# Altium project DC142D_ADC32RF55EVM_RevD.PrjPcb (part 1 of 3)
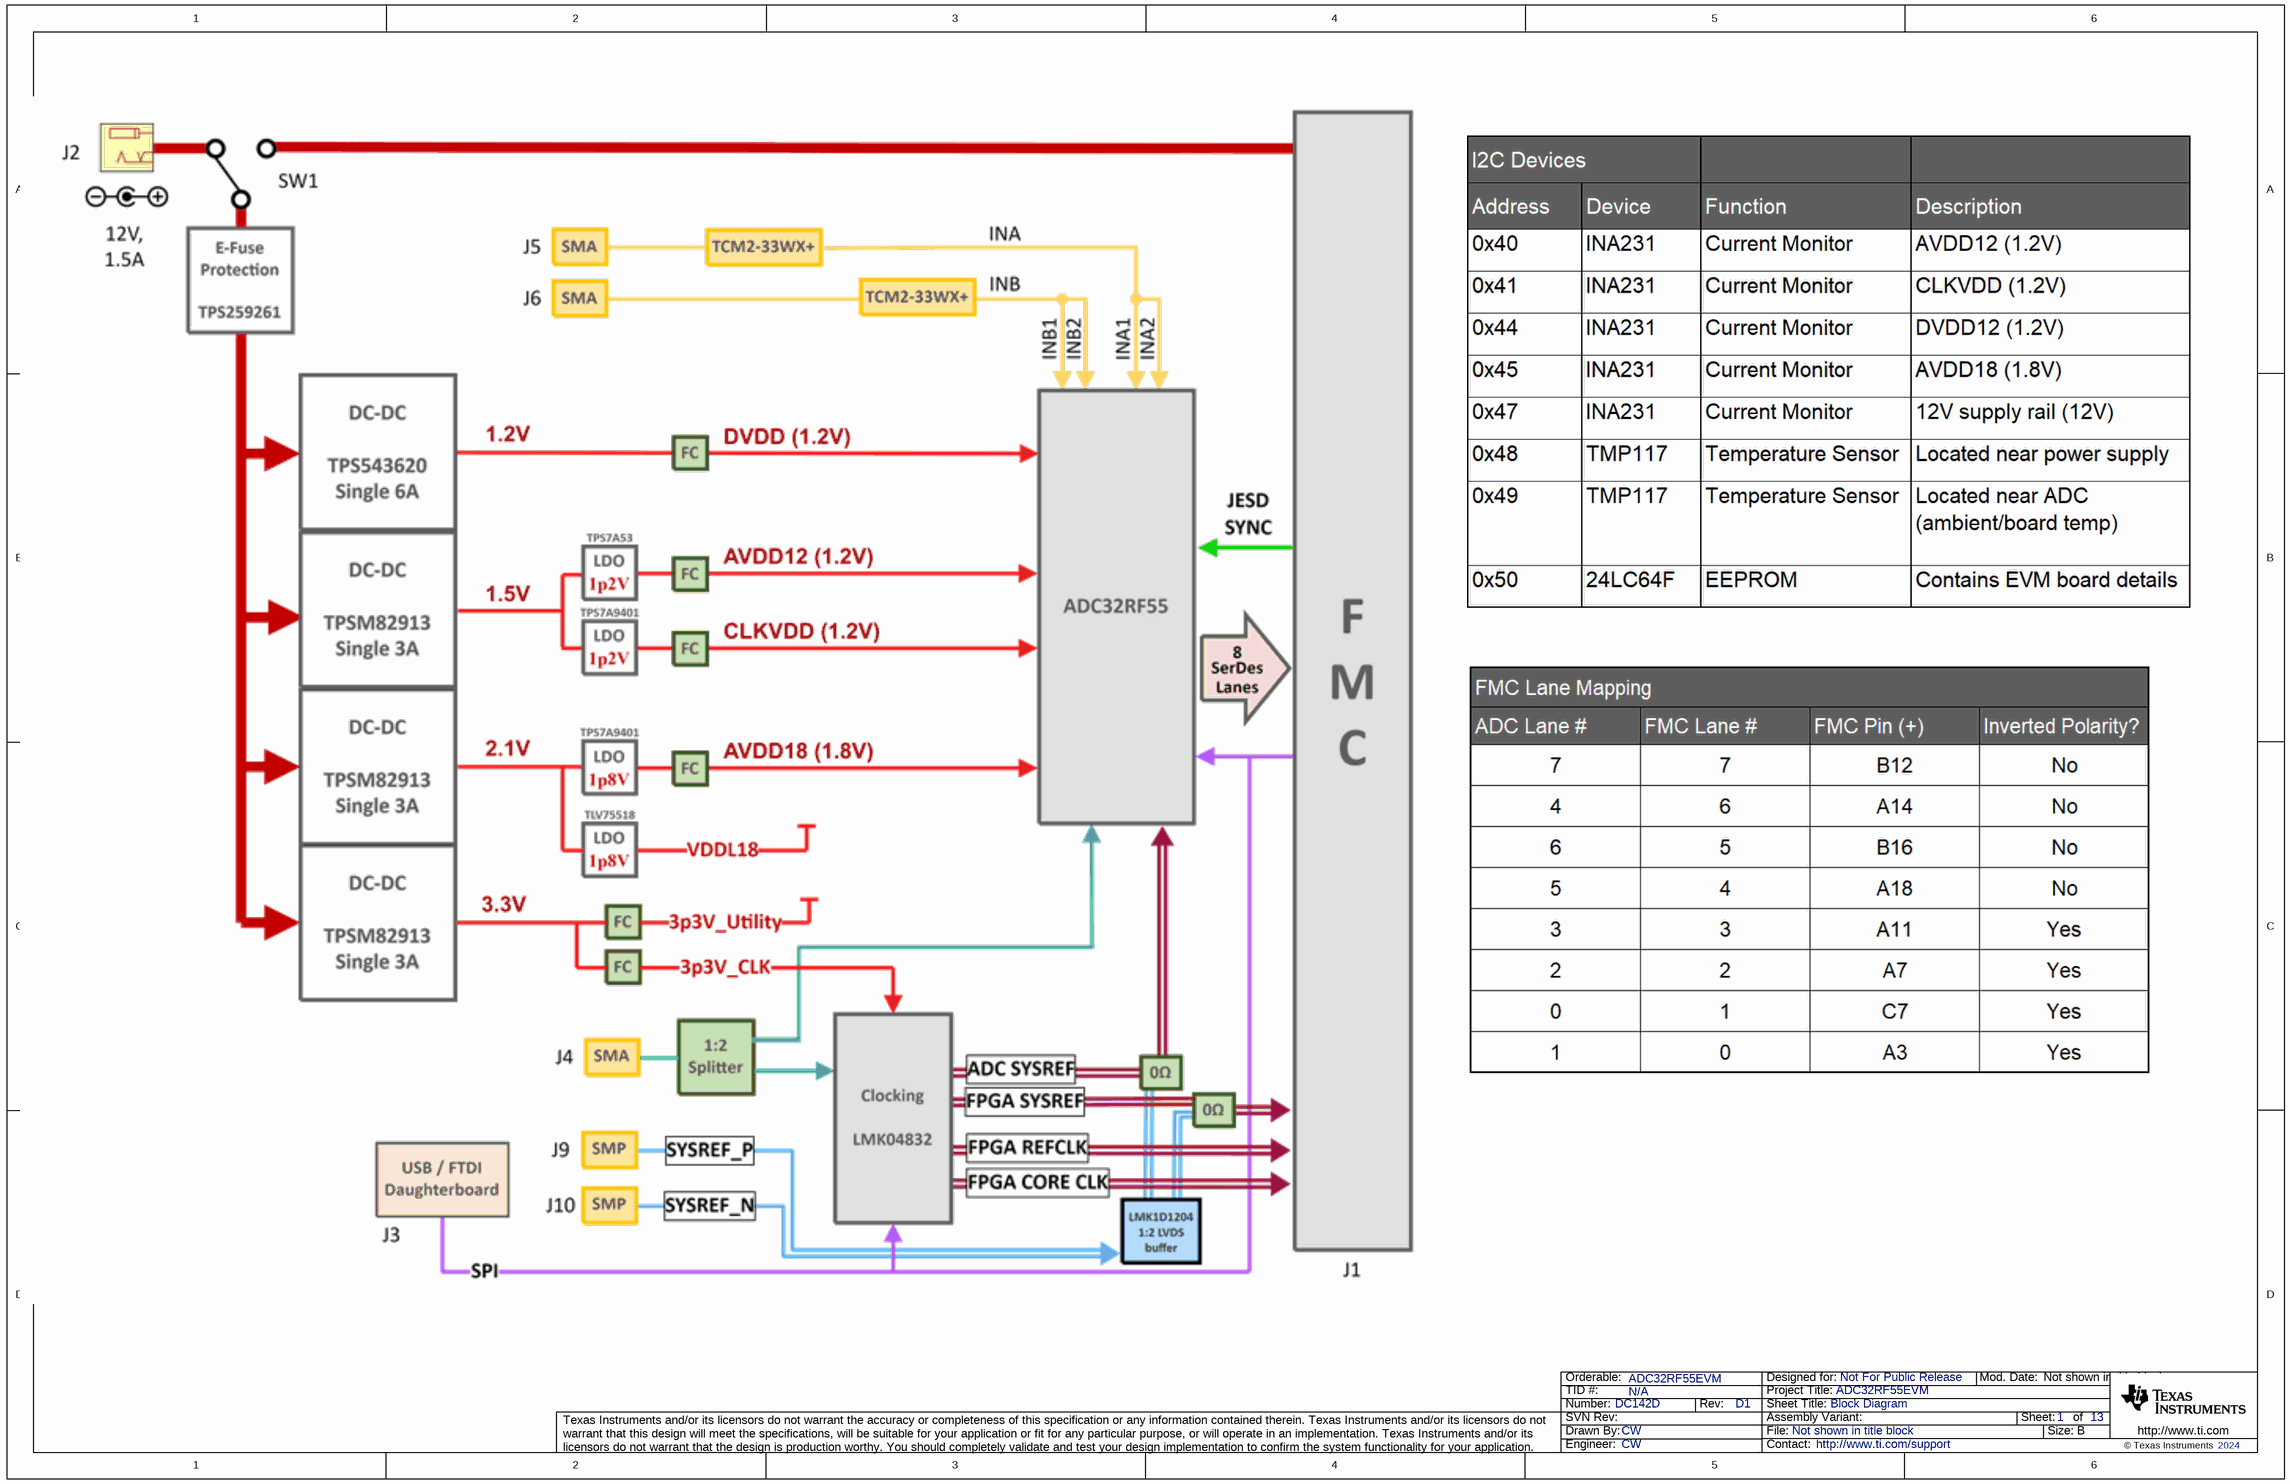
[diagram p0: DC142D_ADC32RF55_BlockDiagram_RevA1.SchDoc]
BrdNum: DC142; CopyrightYear: 2024; EVM_Orderable: ADC32RF55EVM; PCB_Layout: CW; PCB_Rev: D1; PRJ_Customer: Not For Public Release; PRJ_Engineer: CW; PRJ_Number: DC142D; PRJ_Title: ADC32RF55EVM; SCH_Rev: D1; TechSupport: http://www.ti.com/support; TID: N/A
13 sheets, 433 parts. Net scope: flat (ports and power ports of the same name join across sheets).
Board file: ADC32RF55EVM_RevD.PcbDoc
Sheets:
  DC142D_ADC32RF55_BlockDiagram_RevA1.SchDoc
  DC142D_ADC32RF55_Power1_RevA1.SchDoc
  DC142D_ADC32RF55_Power2_RevA1.SchDoc
  DC142D_ADC32RF55_Power3_RevA1.SchDoc
  DC142D_ADC32RF55_USB_RevA1.SchDoc
  DC142D_ADC32RF55_MUX_RevA1.SchDoc
  DC142D_ADC32RF55_ADC_Input_RevA1.SchDoc
  DC142D_ADC32RF55_ADC_Dig_RevA1.SchDoc
  DC142D_ADC32RF55_ADC_Power_RevA1.SchDoc
  DC142D_ADC32RF55_LMK_RevA1.SchDoc
  DC142D_ADC32RF55_FMC_RevA1.SchDoc
  DC142D_ADC32RF55_Misc_RevA1.SchDoc
  DC142D_ADC32RF55_Revision History.SchDoc

## Sheet DC142D_ADC32RF55_BlockDiagram_RevA1.SchDoc: Block Diagram
size 431 x 279 mm; Date: Not shown in title block; ApprovedBy: Not shown in title block; CheckedBy: Not shown in title block; Author: Not shown in title block; CompanyName: Not shown in title block; DrawnBy: CW; Engineer: Not shown in title block; Organization: Not shown in title block; Address1: Not shown in title block; Address2: Not shown in title block; Address3: Not shown in title block; Address4: Not shown in title block; DocumentNumber: 1; Revision: Use project parameter SCH_Rev; SheetNumber: 1; SheetTotal: 13; PageSetup: Record=PageOptions¦CenterHorizontal=True¦CenterVertical=True¦PrintScale=1.00¦XCorrection=1.00¦YCorrection=1.00¦PrintKind=0¦BorderSize=5000000¦LeftOffset=0¦BottomOffset=0¦Orientation=2¦PaperLength=1000¦PaperWidth=1000¦Scale=100¦PaperSource=15¦PrintQuality=600¦MediaType=1¦DitherType=10¦PaperKind=Letter¦PrintScaleMode=1

## Sheet DC142D_ADC32RF55_Power1_RevA1.SchDoc: EVM Power 1
size 431 x 279 mm; Date: Not shown in title block; ApprovedBy: Not shown in title block; CheckedBy: Not shown in title block; Author: Not shown in title block; CompanyName: Not shown in title block; DrawnBy: CW; Engineer: Not shown in title block; Organization: Not shown in title block; Address1: Not shown in title block; Address2: Not shown in title block; Address3: Not shown in title block; Address4: Not shown in title block; DocumentNumber: 6; Revision: Use project parameter SCH_Rev; SheetNumber: 2; SheetTotal: 13; PageSetup: Record=PageOptions¦CenterHorizontal=True¦CenterVertical=True¦PrintScale=1.00¦XCorrection=1.00¦YCorrection=1.00¦PrintKind=0¦BorderSize=5000000¦LeftOffset=0¦BottomOffset=0¦Orientation=2¦PaperLength=1000¦PaperWidth=1000¦Scale=100¦PaperSource=15¦PrintQuality=600¦MediaType=1¦DitherType=10¦PaperKind=Letter¦PrintScaleMode=1
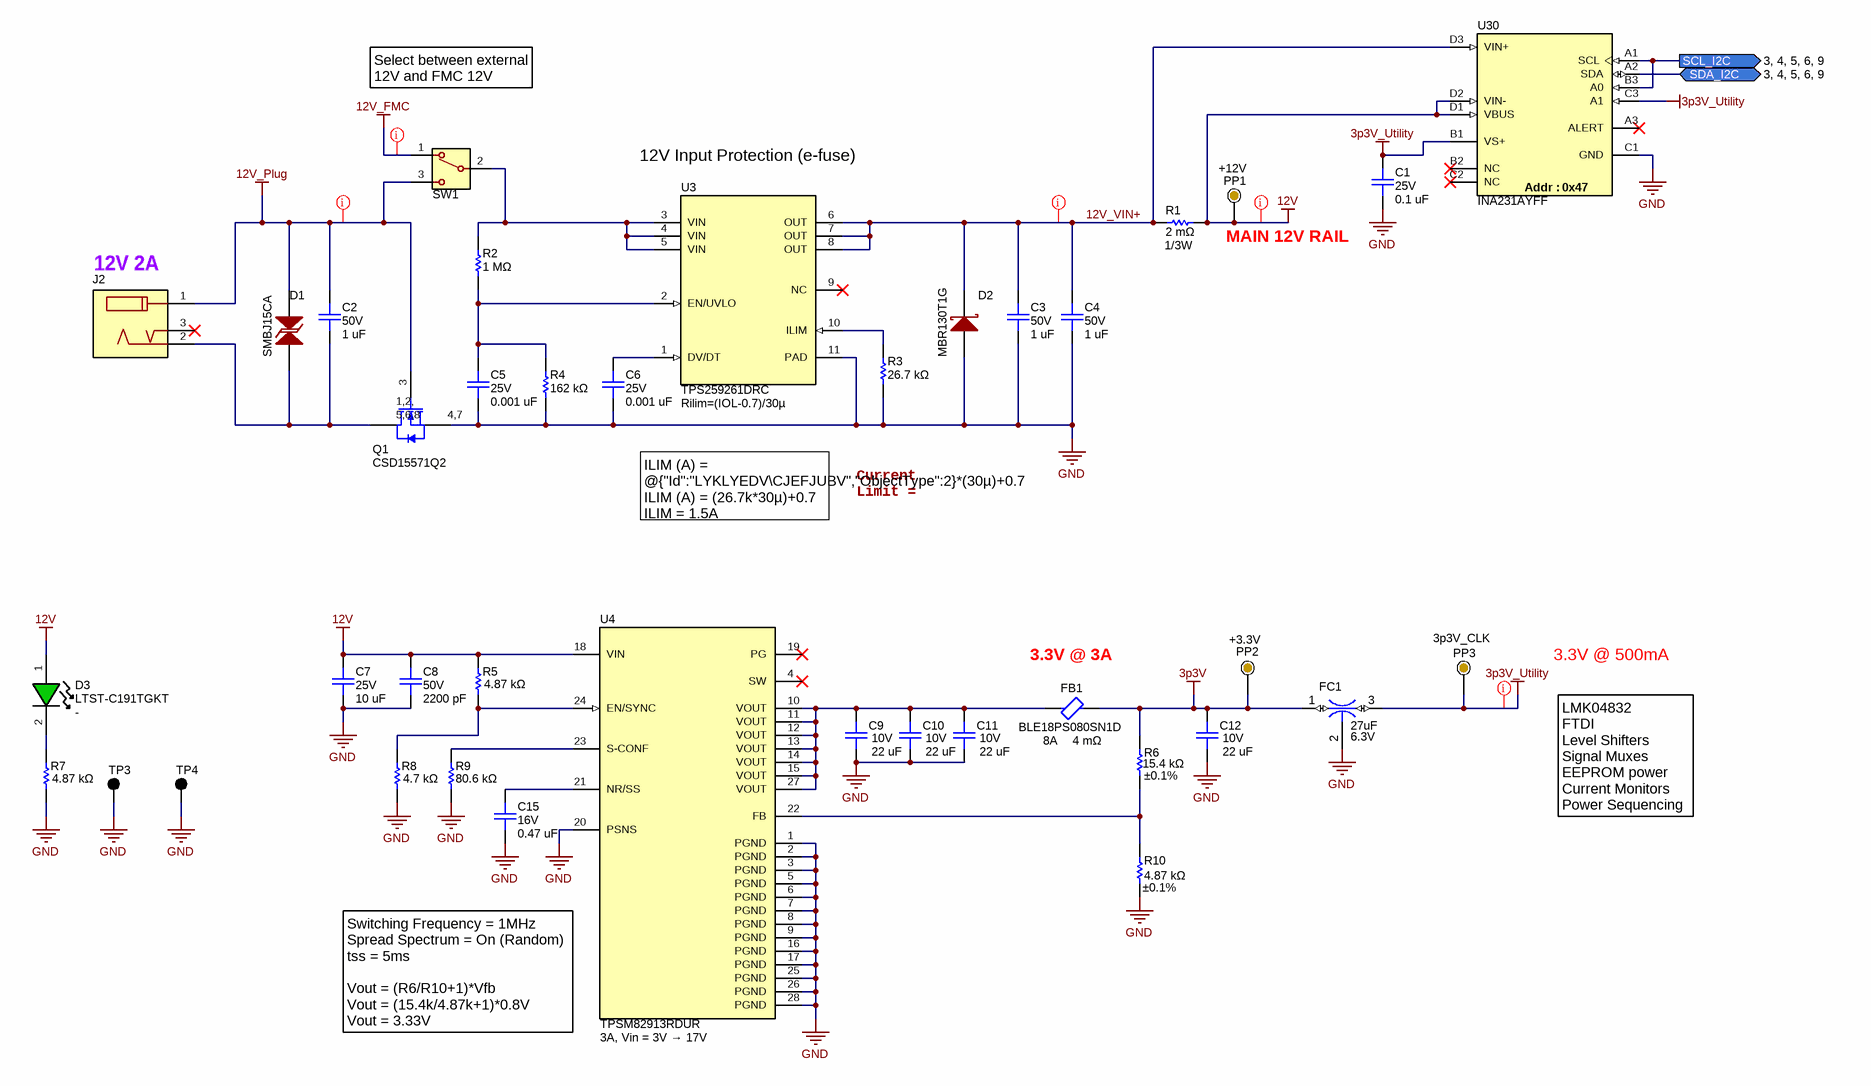
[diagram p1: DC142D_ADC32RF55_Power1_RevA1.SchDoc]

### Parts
C1  value 0.1 uF  Voltage - Rated: 25V  [0402L_cap]  (hidden comment: 04023C104JAT2A)
C2  value 1 uF  Voltage - Rated: 50V  [0805L_cap]  (hidden comment: C2012X7R1H105K125AB)
C3  value 1 uF  Voltage - Rated: 50V  [0805L_cap]  (hidden comment: C2012X7R1H105K125AB)
C4  value 1 uF  Voltage - Rated: 50V  [0805L_cap]  (hidden comment: C2012X7R1H105K125AB)
C5  value 0.001 uF  Voltage - Rated: 25V  [0201_cap]  (hidden comment: 02013C102KAT2A)
C6  value 0.001 uF  Voltage - Rated: 25V  [0201_cap]  (hidden comment: 02013C102KAT2A)
C7  value 10 uF  Voltage - Rated: 25V  [0805L_cap]  (hidden comment: C2012X7S1E106K125AC)
C8  value 2200 pF  Voltage - Rated: 50V  [0402L_cap]  (hidden comment: 04025C222JAT2A)
C9  value 22 uF  Voltage - Rated: 10V  [0805L_cap]  (hidden comment: C2012X7S1A226M125AC)
C10  value 22 uF  Voltage - Rated: 10V  [0805L_cap]  (hidden comment: C2012X7S1A226M125AC)
C11  value 22 uF  Voltage - Rated: 10V  [0805L_cap]  (hidden comment: C2012X7S1A226M125AC)
C12  value 22 uF  Voltage - Rated: 10V  [0805L_cap]  (hidden comment: C2012X7S1A226M125AC)
C15  value 0.47 uF  Voltage - Rated: 16V  [0402L_cap]  (hidden comment: CGA2B1X7S1C474K050BC)
D1  SMBJ15CA  [SMBJ15CA]
D2  MBR130T1G  [SOD-123]
D3  LTST-C191TGKT  [LED_LTST-C190-Green]
FB1  BLE18PS080SN1D  Current: 8A  DCR: 4 mΩ  [0603L]
FC1  value 27uF  Voltage - Rated: 6.3V  [NFM31PC]  (hidden comment: dcp00001)
J2  RAPC722X  [RAPC722X]  (value not drawn)
PP1  Text1: +12V  [ProbePoint_TH_40mil]  (hidden comment: Probe Point)  (no BOM)
PP2  Text1: +3.3V  [ProbePoint_TH_40mil]  (hidden comment: Probe Point)  (no BOM)
PP3  Text1: 3p3V_CLK  [ProbePoint_TH_40mil]  (hidden comment: Probe Point)  (no BOM)
Q1  CSD15571Q2  [DQK0006C]
R1  value 2 mΩ  Power (Watts): 1/3W  [CCS0603FLxLxx]  (hidden comment: CSS0603FT2L00)
R2  value 1 MΩ  [0201]  (hidden comment: ERJ-1GNF1004C)
R3  value 26.7 kΩ  [0201]  (hidden comment: ERJ-1GNF2672C)
R4  value 162 kΩ  [0402L]  (hidden comment: ERJ-2RKF1623X)
R5  value 4.87 kΩ  [0402L]  (hidden comment: ERJ-2RKF4871X)
R6  value 15.4 kΩ  Tolerance: ±0.1%  [0402L]  (hidden comment: ERA-2APB1542X)
R7  value 4.87 kΩ  [0402L]  (hidden comment: ERJ-2RKF4871X)
R8  value 4.7 kΩ  [0402L]  (hidden comment: ERJ-PA2F4701X)
R9  value 80.6 kΩ  [0402L]  (hidden comment: ERJ-2RKF8062X)
R10  value 4.87 kΩ  Tolerance: ±0.1%  [0402L]  (hidden comment: ERA-2APB4871X)
SW1  1101M2S3CGE2  [FP-1101M2S3CGE2_SIP3-MFG]  (value not drawn)
TP3  5011  [Keystone5011]  (value not drawn)
TP4  5011  [Keystone5011]  (value not drawn)
U3  TPS259261DRC  Text1: Rilim=(IOL-0.7)/30µ  [DRC0010J]
U4  TPSM82913RDUR  Text1: 3A, Vin = 3V → 17V  [RDU0028A]
U30  INA231AYFF  Address: 0x47  [YFF0012AKAD]

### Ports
SCL_I2C (out, see 3, 4, 5, 6, 9), SDA_I2C (bidir, see 3, 4, 5, 6, 9)

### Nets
3p3V: C12.2 FB1.2 FC1.1 PP2.1 R6.2
3p3V_Utility: C1.2 FC1.3 PP3.1 U30.B1(VS+) U30.C3(A1)
12V: C7.2 C8.2 D3.1(A) PP1.1 R1.2 R5.1 U4.18(VIN) U30.D1(VBUS) U30.D2(VIN-)
12V_FMC: SW1.1
12V_Plug: C2.1 D1.2 J2.1 Q1.3(G) SW1.3
GND: C1.1 C3.2 C4.2 C5.1 C6.1 C7.1 C8.1 C9.1 C10.1 C11.1 C12.1 C15.1 D2.2(A) FC1.2 Q1.4,7(S) R3.1 R4.2 R7.2 R8.2 R9.1 R10.1 TP3.1 TP4.1 U3.11(PAD) U4.1(PGND) U4.2(PGND) U4.3(PGND) U4.5(PGND) U4.6(PGND) U4.7(PGND) U4.8(PGND) U4.9(PGND) U4.16(PGND) U4.17(PGND) U4.20(PSNS) U4.25(PGND) U4.26(PGND) U4.28(PGND) U30.C1(GND)
12V_VIN+: C3.1 C4.1 D2.1(K) R1.1 U3.6(OUT) U3.7(OUT) U3.8(OUT) U30.D3(VIN+)
SCL_I2C: U30.A1(SCL) U30.B3(A0) ; port SCL_I2C
SDA_I2C: U30.A2(SDA) ; port SDA_I2C
NetC2_2: C2.2 D1.1 J2.2 Q1.1,2,5,6,8(D)
NetC5_2: C5.2 R2.1 R4.1 U3.2(EN/UVLO)
NetC6_2: C6.2 U3.1(DV/DT)
NetC9_2: C9.2 C10.2 C11.2 FB1.1 U4.10(VOUT) U4.11(VOUT) U4.12(VOUT) U4.13(VOUT) U4.14(VOUT) U4.15(VOUT) U4.27(VOUT)
NetC15_2: C15.2 U4.21(NR/SS)
NetD3_2: D3.2(K) R7.1
NetR2_2: R2.2 SW1.2(COMM) U3.3(VIN) U3.4(VIN) U3.5(VIN)
NetR3_2: R3.2 U3.10(ILIM)
NetR5_2: R5.2 R8.1 U4.24(EN/SYNC)
NetR6_1: R6.1 R10.2 U4.22(FB)
NetR9_2: R9.2 U4.23(S-CONF)

Not connected (* = marked no-connect by the designer): J2 3*; U3 9(NC)*; U4 4(SW)* 19(PG)*; U30 A3(ALERT)* B2(NC)* C2(NC)*

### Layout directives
net class Power: 3p3V_Utility, 12V, 12V_FMC, 12V_Plug, 12V_VIN+

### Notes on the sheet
- Select between external 12V and FMC 12V
- 12V Input Protection (e-fuse)
- (near J2) 12V 2A
- MAIN 12V RAIL
- ILIM (A) = @{"Id":"LYKLYEDV\CJEFJUBV","ObjectType":2}*(30µ)+0.7
  ILIM (A) = (26.7k*30µ)+0.7
  ILIM = 1.5A
- Current Limit = 1.5A
- (near FB1) 3.3V @ 3A
- 3.3V @ 500mA
- LMK04832
  FTDI
  Level Shifters
  Signal Muxes
  EEPROM power
  Current Monitors
  Power Sequencing
- (near U4) Switching Frequency = 1MHz
  Spread Spectrum = On (Random)
  tss = 5ms
  Vout = (R6/R10+1)*Vfb
  Vout = (15.4k/4.87k+1)*0.8V
  Vout = 3.33V

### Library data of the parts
C1 = capcc01380: CAP CER 0.1UF 25V X7R 0402; Manufacturer: KYOCERA AVX; CompType: Capacitor Ceramic; Tolerance: ±5%; SizeX_mm: 1; SizeY_mm: 0.5; SizeZ_mm: 0.56
C2-C4 = capcc02687: CAP CER 1UF 50V X7R 0805; Manufacturer: TDK Corporation; CompType: Capacitor Ceramic; Tolerance: ±10%; SizeX_mm: 2; SizeY_mm: 1.25; SizeZ_mm: 1.45
C5 C6 = capcc03754: CAP CER 1000PF 25V X7R 0201; Manufacturer: KYOCERA AVX; CompType: Capacitor Ceramic; Tolerance: ±10%; SizeX_mm: 0.6; SizeY_mm: 0.3; SizeZ_mm: 0.33
C7 = capcc03511: CAP CER 10UF 25V X7S 0805; Manufacturer: TDK Corporation; CompType: Capacitor Ceramic; Tolerance: ±10%; SizeX_mm: 2; SizeY_mm: 1.25; SizeZ_mm: 1.5
C8 = capcc04216: CAP CER 2200PF 50V X7R 0402; Manufacturer: KYOCERA AVX; CompType: Capacitor Ceramic; Tolerance: ±5%; SizeX_mm: 1; SizeY_mm: 0.5; SizeZ_mm: 0.56
C9-C12 = capcc09395: CAP CER 22UF 10V X7S 0805; Manufacturer: TDK Corporation; SizeZ_mm: 1.45; SizeX_mm: 2; SizeY_mm: 1.25; CompType: Capacitor Ceramic; Tolerance: ±20%
C15 = capcc02208: CAP CER 0.47UF 16V X7S 0402; Manufacturer: TDK Corporation; CompType: Capacitor Ceramic; Tolerance: ±10%; SizeX_mm: 1; SizeY_mm: 0.5; SizeZ_mm: 0.55
D1 = cmp00440: 24.4V Clamp 24.6A Ipp Tvs Diode; Manufacturer: Littlefuse; CompType: Diode TVS
D2 = cmp00438: DIODE SCHOTTKY 30V 1A SOD123; Manufacturer: Onsemi; Alt PartNumber: RB160M-30TR; Alt Manufacturer: Rohm Semiconductor
D3 = cmp00247: LED GREEN CLEAR CHIP SMD; Manufacturer: Lite-On Inc.; Current Rating (Amps): 20mA; Voltage - Forward (Vf) (Typ): 3.2V; SizeX_mm: 1.6; SizeY_mm: 0.8; SizeZ_mm: 0.65
FB1 = dcp00004: 8.5 Ohms @ 100 MHz 1 Power Line Ferrite Bead 0603 (1608 Metric) 8A 4mOhm; Manufacturer: Murata; Impedance: 8.5 Ω; SizeX_mm: 1.6; SizeY_mm: 0.8
FC1 = dcp00001: Feed through capactior 27uF; PartNumber: NFM31PC276B0J3L; Manufacturer: Murata; CompType: Feed Thru Cap; Tolerance: ±20%; SizeX_mm: 3.2; SizeY_mm: 1.6; SizeZ_mm: 1.5; Current: 6A; DCR: 5 mΩ
J2 = RAPC722X: Power Jack, mini, 2.1mm OD, R/A, TH; Manufacturer: Switchcraft; UniqueID: cmp00022
PP1-PP3 = cmp00025: Probe Point that can be used in lue of a test point
Q1 = cmp00159: MOSFET, N-CH, 20 V, 10 A; Manufacturer: Texas Instruments; CompType: FET
R1 = OtherRs00002: RES SHUNT, 0603, 0.002 OHM, 1%,; Manufacturer: Stackpole Electronics Inc; CompType: Resistor SMD Sense; Temperature Coefficient: ±150ppm/°C; SizeX_mm: 1.6; SizeY_mm: 0.8; SizeZ_mm: 0.65
R2 = RSMD020101018: RES SMD 1M OHM 1% 1/20W 0201; Manufacturer: Panasonic Electronic Components; CompType: Resistor SMD; Power (Watts): 0.05W, 1/20W; Temperature Coefficient: ±200ppm/°C
R3 = RSMD020100623: RES SMD 26.7K OHM 1% 1/20W 0201; Manufacturer: Panasonic Electronic Components; CompType: Resistor SMD; Power (Watts): 0.05W, 1/20W; Temperature Coefficient: ±200ppm/°C
R4 = RSMD040200945: RES SMD 162K OHM 1% 1/10W 0402; Manufacturer: Panasonic Electronic Components; CompType: Resistor SMD; Power (Watts): 0.1W, 1/10W; Temperature Coefficient: ±100ppm/°C; SizeX_mm: 1; SizeY_mm: 0.5; SizeZ_mm: 0.4
R5 R7 = RSMD040202616: RES SMD 4.87K OHM 1% 1/10W 0402; Manufacturer: Panasonic Electronic Components; CompType: Resistor SMD; Power (Watts): 0.1W, 1/10W; Temperature Coefficient: ±100ppm/°C; SizeX_mm: 1; SizeY_mm: 0.5; SizeZ_mm: 0.4
R6 = RSMD040200802: RES SMD 15.4KOHM 0.1% 1/16W 0402; Manufacturer: Panasonic Electronic Components; SizeX_mm: 1; SizeY_mm: 0.5; SizeZ_mm: 0.4; CompType: Resistor SMD; Power (Watts): 0.063W, 1/16W; Temperature Coefficient: ±15ppm/°C
R8 = RSMD040202587: RES SMD 4.7K OHM 1% 1/5W 0402; Manufacturer: Panasonic Electronic Components; CompType: Resistor SMD; Power (Watts): 0.2W, 1/5W; Temperature Coefficient: ±100ppm/°C; SizeX_mm: 1; SizeY_mm: 0.5; SizeZ_mm: 0.4
R9 = RSMD040203748: RES SMD 80.6K OHM 1% 1/10W 0402; Manufacturer: Panasonic Electronic Components; CompType: Resistor SMD; Power (Watts): 0.1W, 1/10W; Temperature Coefficient: ±100ppm/°C; SizeX_mm: 1; SizeY_mm: 0.5; SizeZ_mm: 0.4
R10 = RSMD040202614: RES SMD 4.87KOHM 0.1% 1/16W 0402; Manufacturer: Panasonic Electronic Components; SizeX_mm: 1; SizeY_mm: 0.5; SizeZ_mm: 0.4; CompType: Resistor SMD; Power (Watts): 0.063W, 1/16W; Temperature Coefficient: ±15ppm/°C
SW1 = 1101M2S3CGE2: Switch Slide SPDT 120V, 6A; Manufacturer: C&K Components; UniqueID: cmp00021; Text1: Silk1; Text2: Silk2; Text3: Silk3
TP3 TP4 = cmp00041: Test Point, Multipurpose, Black, TH; Manufacturer: Keystone; Text1: Silk
U3 = cmp00157: 12V, 5A, 30mΩ eFuse with Adjustable +/-15% Accurate Current Limit, DRC0010J (VSON-10); Manufacturer: Texas Instruments
U4 = cmp00201: 3-V to 17-V, 3-A Low-Noise and Low-Ripple Buck Power Module with Integrated Ferrite Bead Filter Compensation; Manufacturer: Texas Instruments; Switching Frequency: 1/2.2MHz; Max Duty Cycle: 100%; Output Voltage: 0.8-5.5V; Standoff Height: 0mm; CompType: Switcher; Number Of Outputs: 1; Max Supply Voltage: 17V; AEC Category: Q200; TJmax_C: +125°C; Nominal Supply Current: 5mA; Output Type: AdjustableProgrammable; Min Supply Voltage: 3V; AEC Qualified: No
U30 = INA231AYFF: 28-V, 16-Bit, I2C Output Current, Voltage and Power Monitor With Alert in WCSP Package; PartNumber: INA231AIYFFT; Manufacturer: Texas Instruments; Pitch (mm): 0.4

## Sheet DC142D_ADC32RF55_Power2_RevA1.SchDoc: EVM Power 2
size 431 x 279 mm; Date: Not shown in title block; ApprovedBy: Not shown in title block; CheckedBy: Not shown in title block; Author: Not shown in title block; CompanyName: Not shown in title block; DrawnBy: CW; Engineer: Not shown in title block; Organization: Not shown in title block; Address1: Not shown in title block; Address2: Not shown in title block; Address3: Not shown in title block; Address4: Not shown in title block; DocumentNumber: 7; Revision: Use project parameter SCH_Rev; SheetNumber: 3; SheetTotal: 13; PageSetup: Record=PageOptions¦CenterHorizontal=True¦CenterVertical=True¦PrintScale=1.00¦XCorrection=1.00¦YCorrection=1.00¦PrintKind=0¦BorderSize=5000000¦LeftOffset=0¦BottomOffset=0¦Orientation=2¦PaperLength=1000¦PaperWidth=1000¦Scale=100¦PaperSource=15¦PrintQuality=600¦MediaType=1¦DitherType=10¦PaperKind=Letter¦PrintScaleMode=1
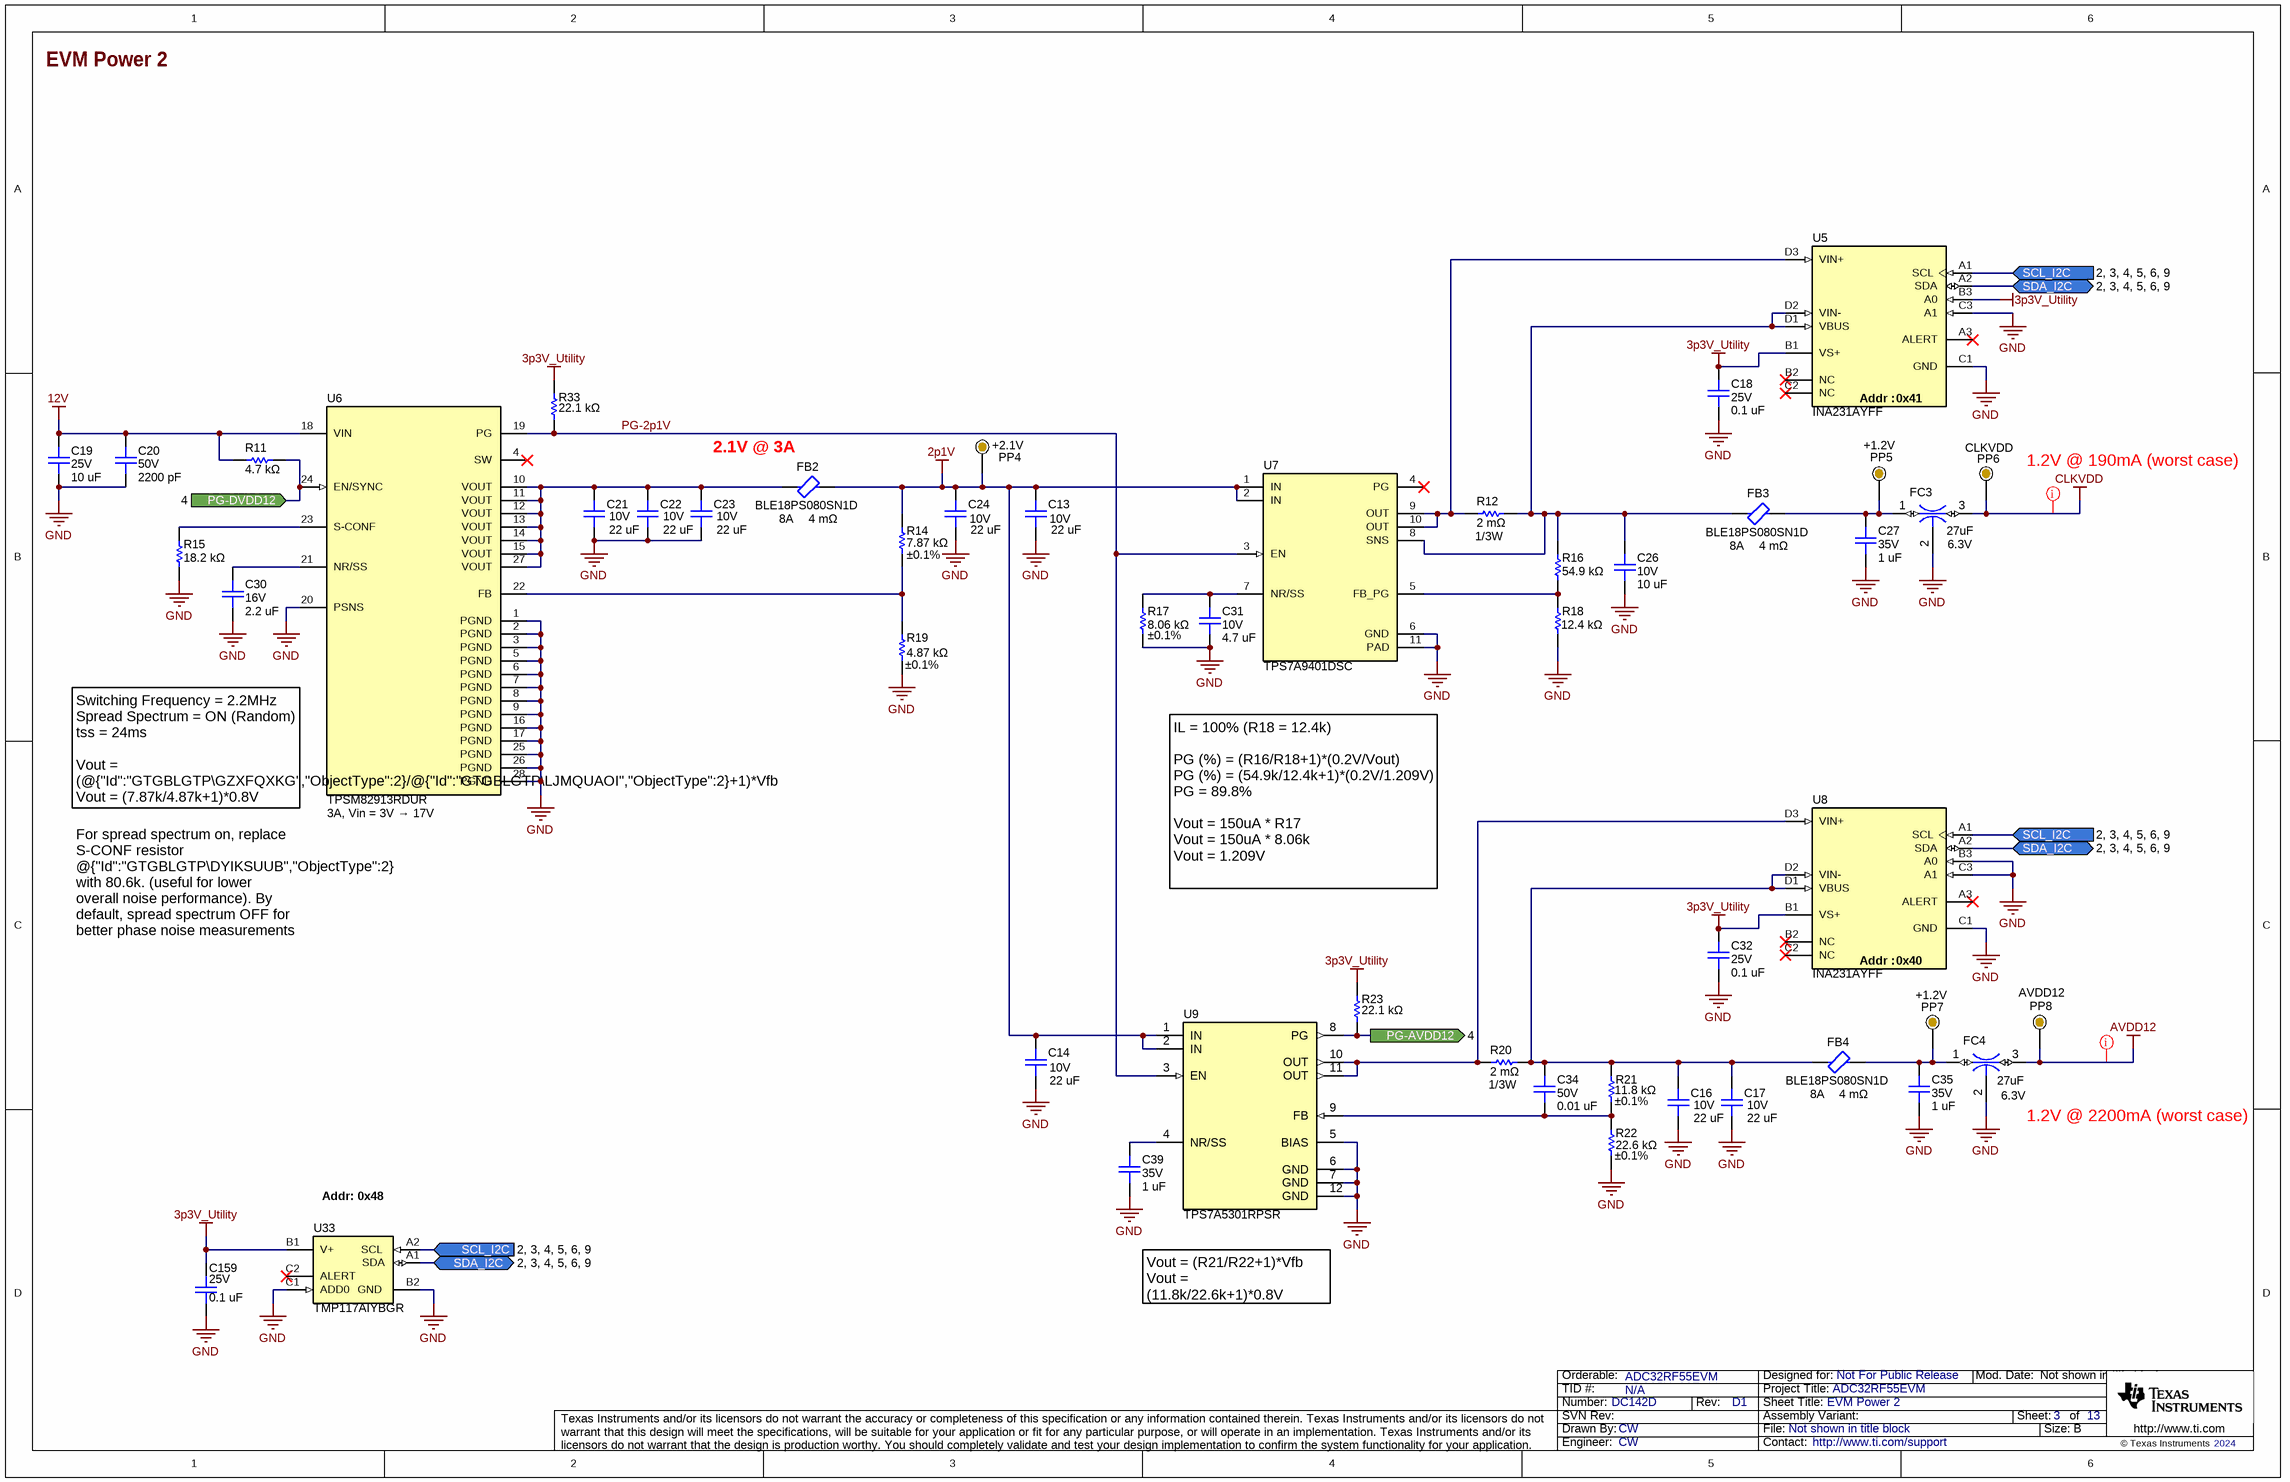
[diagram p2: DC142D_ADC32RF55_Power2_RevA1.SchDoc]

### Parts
C13  value 22 uF  Voltage - Rated: 10V  [0805L_cap]  (hidden comment: C2012X7S1A226M125AC)
C14  value 22 uF  Voltage - Rated: 10V  [0805L_cap]  (hidden comment: C2012X7S1A226M125AC)
C16  value 22 uF  Voltage - Rated: 10V  [0805L_cap]  (hidden comment: C2012X7S1A226M125AC)
C17  value 22 uF  Voltage - Rated: 10V  [0805L_cap]  (hidden comment: C2012X7S1A226M125AC)
C18  value 0.1 uF  Voltage - Rated: 25V  [0402L_cap]  (hidden comment: 04023C104JAT2A)
C19  value 10 uF  Voltage - Rated: 25V  [0805L_cap]  (hidden comment: C2012X7S1E106K125AC)
C20  value 2200 pF  Voltage - Rated: 50V  [0402L_cap]  (hidden comment: 04025C222JAT2A)
C21  value 22 uF  Voltage - Rated: 10V  [0805L_cap]  (hidden comment: C2012X7S1A226M125AC)
C22  value 22 uF  Voltage - Rated: 10V  [0805L_cap]  (hidden comment: C2012X7S1A226M125AC)
C23  value 22 uF  Voltage - Rated: 10V  [0805L_cap]  (hidden comment: C2012X7S1A226M125AC)
C24  value 22 uF  Voltage - Rated: 10V  [0805L_cap]  (hidden comment: C2012X7S1A226M125AC)
C26  value 10 uF  Voltage - Rated: 10V  [0402L_cap]  (hidden comment: 0402ZD106MAT2A)
C27  value 1 uF  Voltage - Rated: 35V  [0402L_cap]  (hidden comment: C1005X5R1V105K050BE)
C30  value 2.2 uF  Voltage - Rated: 16V  [0402L_cap]  (hidden comment: C1005X6S1C225K050BC)
C31  value 4.7 uF  Voltage - Rated: 10V  [0402L_cap]  (hidden comment: C1005X5R1A475K050BE)
C32  value 0.1 uF  Voltage - Rated: 25V  [0402L_cap]  (hidden comment: 04023C104JAT2A)
C34  value 0.01 uF  Voltage - Rated: 50V  [0402L_cap]  (hidden comment: 04025C103MAT2A)
C35  value 1 uF  Voltage - Rated: 35V  [0402L_cap]  (hidden comment: C1005X5R1V105K050BE)
C39  value 1 uF  Voltage - Rated: 35V  [0402L_cap]  (hidden comment: C1005X5R1V105K050BE)
C159  value 0.1 uF  Voltage - Rated: 25V  [0201_cap]  (hidden comment: C0603X5R1E104K030BB)
FB2  BLE18PS080SN1D  Current: 8A  DCR: 4 mΩ  [0603L]
FB3  BLE18PS080SN1D  Current: 8A  DCR: 4 mΩ  [0603L]
FB4  BLE18PS080SN1D  Current: 8A  DCR: 4 mΩ  [0603L]
FC3  value 27uF  Voltage - Rated: 6.3V  [NFM31PC]  (hidden comment: dcp00001)
FC4  value 27uF  Voltage - Rated: 6.3V  [NFM31PC]  (hidden comment: dcp00001)
PP4  Text1: +2.1V  [ProbePoint_TH_40mil]  (hidden comment: Probe Point)  (no BOM)
PP5  Text1: +1.2V  [ProbePoint_TH_40mil]  (hidden comment: Probe Point)  (no BOM)
PP6  Text1: CLKVDD  [ProbePoint_TH_40mil]  (hidden comment: Probe Point)  (no BOM)
PP7  Text1: +1.2V  [ProbePoint_TH_40mil]  (hidden comment: Probe Point)  (no BOM)
PP8  Text1: AVDD12  [ProbePoint_TH_40mil]  (hidden comment: Probe Point)  (no BOM)
R11  value 4.7 kΩ  [0402L]  (hidden comment: ERJ-PA2F4701X)
R12  value 2 mΩ  Power (Watts): 1/3W  [CCS0603FLxLxx]  (hidden comment: CSS0603FT2L00)
R14  value 7.87 kΩ  Tolerance: ±0.1%  [0402L]  (hidden comment: ERA-2ARB7871X)
R15  value 18.2 kΩ  [0402L]  (hidden comment: ERJ-2RKF1822X)
R16  value 54.9 kΩ  [0402L]  (hidden comment: ERJ-2RKF5492X)
R17  value 8.06 kΩ  Tolerance: ±0.1%  [0402L]  (hidden comment: ERA-2APB8061X)
R18  value 12.4 kΩ  [0402L]  (hidden comment: ERJ-2RKF1242X)
R19  value 4.87 kΩ  Tolerance: ±0.1%  [0402L]  (hidden comment: ERA-2APB4871X)
R20  value 2 mΩ  Power (Watts): 1/3W  [CCS0603FLxLxx]  (hidden comment: CSS0603FT2L00)
R21  value 11.8 kΩ  Tolerance: ±0.1%  [0402L]  (hidden comment: ERA-2AEB1182X)
R22  value 22.6 kΩ  Tolerance: ±0.1%  [0402L]  (hidden comment: ERA-2ARB2262X)
R23  Resistance: 22.1 kΩ  [0402L]  (hidden comment: ERJ-2RKF2212X)
R33  Resistance: 22.1 kΩ  [0402L]  (hidden comment: ERJ-2RKF2212X)
U5  INA231AYFF  Address: 0x41  [YFF0012AKAD]
U6  TPSM82913RDUR  Text1: 3A, Vin = 3V → 17V  [RDU0028A]
U7  TPS7A9401DSC  [DSC0010]
U8  INA231AYFF  Address: 0x40  [YFF0012AKAD]
U9  TPS7A5301RPSR  [RPS0012A-MFG]
U33  TMP117AIYBGR  [YBG0006AJAP]

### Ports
PG-AVDD12 (out, see 4), PG-DVDD12 (in, see 4), SCL_I2C (in, see 2, 3, 4, 5, 6, 9), SDA_I2C (bidir, see 2, 3, 4, 5, 6, 9)

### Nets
2p1V: C13.2 C14.2 C24.2 FB2.2 PP4.1 R14.2 U7.1(IN) U7.2(IN) U9.1(IN) U9.2(IN)
3p3V_Utility: C18.2 C32.2 C159.2 R23.2 R33.2 U5.B1(VS+) U5.B3(A0) U8.B1(VS+) U33.B1(V+)
12V: C19.2 C20.2 R11.1 U6.18(VIN)
AVDD12: FC4.3 PP8.1
CLKVDD: FC3.3 PP6.1
GND: C13.1 C14.1 C16.1 C17.1 C18.1 C19.1 C20.1 C21.1 C22.1 C23.1 C24.1 C26.1 C27.1 C30.1 C31.1 C32.1 C35.1 C39.1 C159.1 FC3.2 FC4.2 R15.1 R17.1 R18.1 R19.1 R22.1 U5.C1(GND) U5.C3(A1) U6.1(PGND) U6.2(PGND) U6.3(PGND) U6.5(PGND) U6.6(PGND) U6.7(PGND) U6.8(PGND) U6.9(PGND) U6.16(PGND) U6.17(PGND) U6.20(PSNS) U6.25(PGND) U6.26(PGND) U6.28(PGND) U7.6(GND) U7.11(PAD) U8.B3(A0) U8.C1(GND) U8.C3(A1) U9.5(BIAS) U9.6(GND) U9.7(GND) U9.12(GND) U33.B2(GND) U33.C1(ADD0)
PG-2p1V: R33.1 U6.19(PG) U7.3(EN) U9.3(EN)
PG-AVDD12: R23.1 U9.8(PG) ; port PG-AVDD12
PG-DVDD12: R11.2 U6.24(EN/SYNC) ; port PG-DVDD12
SCL_I2C: U5.A1(SCL) U8.A1(SCL) U33.A2(SCL) ; port SCL_I2C
SDA_I2C: U5.A2(SDA) U8.A2(SDA) U33.A1(SDA) ; port SDA_I2C
NetC16_2: C16.2 C17.2 C34.2 FB4.1 R20.2 R21.2 U8.D1(VBUS) U8.D2(VIN-)
NetC21_2: C21.2 C22.2 C23.2 FB2.1 U6.10(VOUT) U6.11(VOUT) U6.12(VOUT) U6.13(VOUT) U6.14(VOUT) U6.15(VOUT) U6.27(VOUT)
NetC26_2: C26.2 FB3.1 R12.2 R16.2 U5.D1(VBUS) U5.D2(VIN-) U7.8(SNS)
NetC27_2: C27.2 FB3.2 FC3.1 PP5.1
NetC30_2: C30.2 U6.21(NR/SS)
NetC31_2: C31.2 R17.2 U7.7(NR/SS)
NetC34_1: C34.1 R21.1 R22.2 U9.9(FB)
NetC35_2: C35.2 FB4.2 FC4.1 PP7.1
NetC39_2: C39.2 U9.4(NR/SS)
NetR12_1: R12.1 U5.D3(VIN+) U7.9(OUT) U7.10(OUT)
NetR14_1: R14.1 R19.2 U6.22(FB)
NetR15_2: R15.2 U6.23(S-CONF)
NetR16_1: R16.1 R18.2 U7.5(FB_PG)
NetR20_1: R20.1 U8.D3(VIN+) U9.10(OUT) U9.11(OUT)

Not connected (* = marked no-connect by the designer): U5 A3(ALERT)* B2(NC)* C2(NC)*; U6 4(SW)*; U7 4(PG)*; U8 A3(ALERT)* B2(NC)* C2(NC)*; U33 C2(ALERT)*

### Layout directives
net class Power: AVDD12, CLKVDD

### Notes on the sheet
- 2.1V @ 3A
- (near PP6) 1.2V @ 190mA (worst case)
- (near U6) Switching Frequency = 2.2MHz
  Spread Spectrum = ON (Random)
  tss = 24ms
  Vout = (@{"Id":"GTGBLGTP\GZXFQXKG","ObjectType":2}/@{"Id":"GTGBLGTP\LJMQUAOI","ObjectType":2}+1)*Vfb
  Vout = (7.87k/4.87k+1)*0.8V
  Vout = 2.09V
- IL = 100% (R18 = 12.4k)
  PG (%) = (R16/R18+1)*(0.2V/Vout)
  PG (%) = (54.9k/12.4k+1)*(0.2V/1.209V)
  PG = 89.8%
  Vout = 150uA * R17
  Vout = 150uA * 8.06k
  Vout = 1.209V
- (near U6) For spread spectrum on, replace S-CONF resistor @{"Id":"GTGBLGTP\DYIKSUUB","ObjectType":2} with 80.6k. (useful for lower overall noise performance). By default, spread spectrum OFF for better phase noise measurements
- (near FC4) 1.2V @ 2200mA (worst case)
- (near U33) Addr: 0x48
- Vout = (R21/R22+1)*Vfb
  Vout = (11.8k/22.6k+1)*0.8V
  Vout = 1.217V

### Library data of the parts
C13 C14 C16 C17 C21-C24 = capcc09395: as C9 on sheet DC142D_ADC32RF55_Power1_RevA1
C18 C32 = capcc01380: as C1 on sheet DC142D_ADC32RF55_Power1_RevA1
C19 = capcc03511: as C7 on sheet DC142D_ADC32RF55_Power1_RevA1
C20 = capcc04216: as C8 on sheet DC142D_ADC32RF55_Power1_RevA1
C26 = capcc09406: CAP CER 10UF 10V X5R 0402; Manufacturer: KYOCERA AVX; CompType: Capacitor Ceramic; Tolerance: ±20%; SizeX_mm: 1; SizeY_mm: 0.5; SizeZ_mm: 0.7
C27 C35 C39 = capcc02785: CAP CER 1UF 35V X5R 0402; Manufacturer: TDK Corporation; CompType: Capacitor Ceramic; Tolerance: ±10%; SizeX_mm: 1; SizeY_mm: 0.5; SizeZ_mm: 0.65
C30 = capcc03154: CAP CER 2.2UF 16V X6S 0402; Manufacturer: TDK Corporation; CompType: Capacitor Ceramic; Tolerance: ±10%; SizeX_mm: 1; SizeY_mm: 0.5; SizeZ_mm: 0.65
C31 = capcc03139: CAP CER 4.7UF 10V X5R 0402; Manufacturer: TDK Corporation; CompType: Capacitor Ceramic; Tolerance: ±10%; SizeX_mm: 1; SizeY_mm: 0.5; SizeZ_mm: 0.7
C34 = capcc05466: CAP CER 10000PF 50V X7R 0402; Manufacturer: KYOCERA AVX; CompType: Capacitor Ceramic; Tolerance: ±20%; SizeX_mm: 1; SizeY_mm: 0.5; SizeZ_mm: 0.55
C159 = capcc01294: CAP CER 0.1UF 25V X5R 0201; Manufacturer: TDK Corporation; SizeZ_mm: 0.33; SizeY_mm: 0.3; CompType: Capacitor Ceramic; SizeX_mm: 0.6; Tolerance: ±10%
FB2-FB4 = dcp00004: as FB1 on sheet DC142D_ADC32RF55_Power1_RevA1
FC3 FC4 = dcp00001: as FC1 on sheet DC142D_ADC32RF55_Power1_RevA1
PP4-PP8 = cmp00025: as PP1 on sheet DC142D_ADC32RF55_Power1_RevA1
R11 = RSMD040202587: as R8 on sheet DC142D_ADC32RF55_Power1_RevA1
R12 R20 = OtherRs00002: as R1 on sheet DC142D_ADC32RF55_Power1_RevA1
R14 = RSMD040203578: RES SMD 7.87KOHM 0.1% 1/16W 0402; Manufacturer: Panasonic Electronic Components; CompType: Resistor SMD; Power (Watts): 0.063W, 1/16W; Temperature Coefficient: ±10ppm/°C; SizeX_mm: 1; SizeY_mm: 0.5; SizeZ_mm: 0.4
R15 = RSMD040201047: RES SMD 18.2K OHM 1% 1/10W 0402; Manufacturer: Panasonic Electronic Components; CompType: Resistor SMD; Power (Watts): 0.1W, 1/10W; Temperature Coefficient: ±100ppm/°C; SizeX_mm: 1; SizeY_mm: 0.5; SizeZ_mm: 0.4
R16 = RSMD040203107: RES SMD 54.9K OHM 1% 1/10W 0402; Manufacturer: Panasonic Electronic Components; CompType: Resistor SMD; Power (Watts): 0.1W, 1/10W; Temperature Coefficient: ±100ppm/°C; SizeX_mm: 1; SizeY_mm: 0.5; SizeZ_mm: 0.4
R17 = RSMD040203700: RES SMD 8.06KOHM 0.1% 1/16W 0402; Manufacturer: Panasonic Electronic Components; CompType: Resistor SMD; Power (Watts): 0.063W, 1/16W; Temperature Coefficient: ±15ppm/°C; SizeX_mm: 1; SizeY_mm: 0.5; SizeZ_mm: 0.4
R18 = RSMD040200547: RES SMD 12.4K OHM 1% 1/10W 0402; Manufacturer: Panasonic Electronic Components; CompType: Resistor SMD; Power (Watts): 0.1W, 1/10W; Temperature Coefficient: ±100ppm/°C; SizeX_mm: 1; SizeY_mm: 0.5; SizeZ_mm: 0.4
R19 = RSMD040202614: as R10 on sheet DC142D_ADC32RF55_Power1_RevA1
R21 = RSMD040200444: RES SMD 11.8KOHM 0.1% 1/16W 0402; Manufacturer: Panasonic Electronic Components; CompType: Resistor SMD; Power (Watts): 0.063W, 1/16W; Temperature Coefficient: ±25ppm/°C; SizeX_mm: 1; SizeY_mm: 0.5; SizeZ_mm: 0.4
R22 = RSMD040201486: RES SMD 22.6KOHM 0.1% 1/16W 0402; Manufacturer: Panasonic Electronic Components; CompType: Resistor SMD; Power (Watts): 0.063W, 1/16W; Temperature Coefficient: ±10ppm/°C; SizeX_mm: 1; SizeY_mm: 0.5; SizeZ_mm: 0.4
R23 R33 = RSMD040201481: RES SMD 22.1K OHM 1% 1/10W 0402; Manufacturer: Panasonic Electronic Components; Value: 22.1 kΩ; SizeX_mm: 1; SizeY_mm: 0.5; SizeZ_mm: 0.4; CompType: Resistor SMD; Power (Watts): 0.1W, 1/10W; Temperature Coefficient: ±100ppm/°C
U5 U8 = INA231AYFF: as U30 on sheet DC142D_ADC32RF55_Power1_RevA1
U6 = TPSM82913RDUR: 3-V to 17-V, 3-A Low-Noise and Low-Ripple Buck Power Module with Integrated Ferrite Bead Filter Compensation; Manufacturer: Texas Instruments; Switching Frequency: 1/2.2MHz; Max Duty Cycle: 100%; Output Voltage: 0.8-5.5V; Standoff Height: 0mm; CompType: Switcher; Number Of Outputs: 1; Max Supply Voltage: 17V; AEC Category: Q200; TJmax_C: +125°C; Nominal Supply Current: 5mA; Output Type: AdjustableProgrammable; Min Supply Voltage: 3V; AEC Qualified: No; UniqueID: cmp00201
U7 = cmp00169: 1-A, ultra-low noise, ultra-high PSRR, RF voltage regulator; Manufacturer: Texas Instruments; CompType: LDO; Text1: 1A, Vin 1.7V→5.7V
U9 = TPS7A5301RPSR: Vin 1.1V to 6.5V, 3A, Ultra-Low-Noise, High-PSRR, Low-Dropout Linear Regulator, RPS0012 (VQFN-12); Manufacturer: Texas Instruments; CompType: IC; Vin(Min)(V): 1.1; Rating: Catalog; Vin(Max)(V): 6.5; Vout Adj(Max)(V): 5.15; Vdo(Typ)(mV): 215; Iout(Max)(A): 3
U33 = cmp00348: ±0.1°C accurate digital temperature sensor with integrated NV memory, YBG0006AJAP (DSBGA-6); Manufacturer: Texas Instruments; CompType: Temp Sensor

## Sheet DC142D_ADC32RF55_Power3_RevA1.SchDoc: EVM Power 3
size 431 x 279 mm; Date: Not shown in title block; ApprovedBy: Not shown in title block; CheckedBy: Not shown in title block; Author: Not shown in title block; CompanyName: Not shown in title block; DrawnBy: CW; Engineer: Not shown in title block; Organization: Not shown in title block; Address1: Not shown in title block; Address2: Not shown in title block; Address3: Not shown in title block; Address4: Not shown in title block; DocumentNumber: 8; Revision: Use project parameter SCH_Rev; SheetNumber: 4; SheetTotal: 13; PageSetup: Record=PageOptions¦CenterHorizontal=True¦CenterVertical=True¦PrintScale=1.00¦XCorrection=1.00¦YCorrection=1.00¦PrintKind=0¦BorderSize=5000000¦LeftOffset=0¦BottomOffset=0¦Orientation=2¦PaperLength=1000¦PaperWidth=1000¦Scale=100¦PaperSource=15¦PrintQuality=600¦MediaType=1¦DitherType=10¦PaperKind=Letter¦PrintScaleMode=1
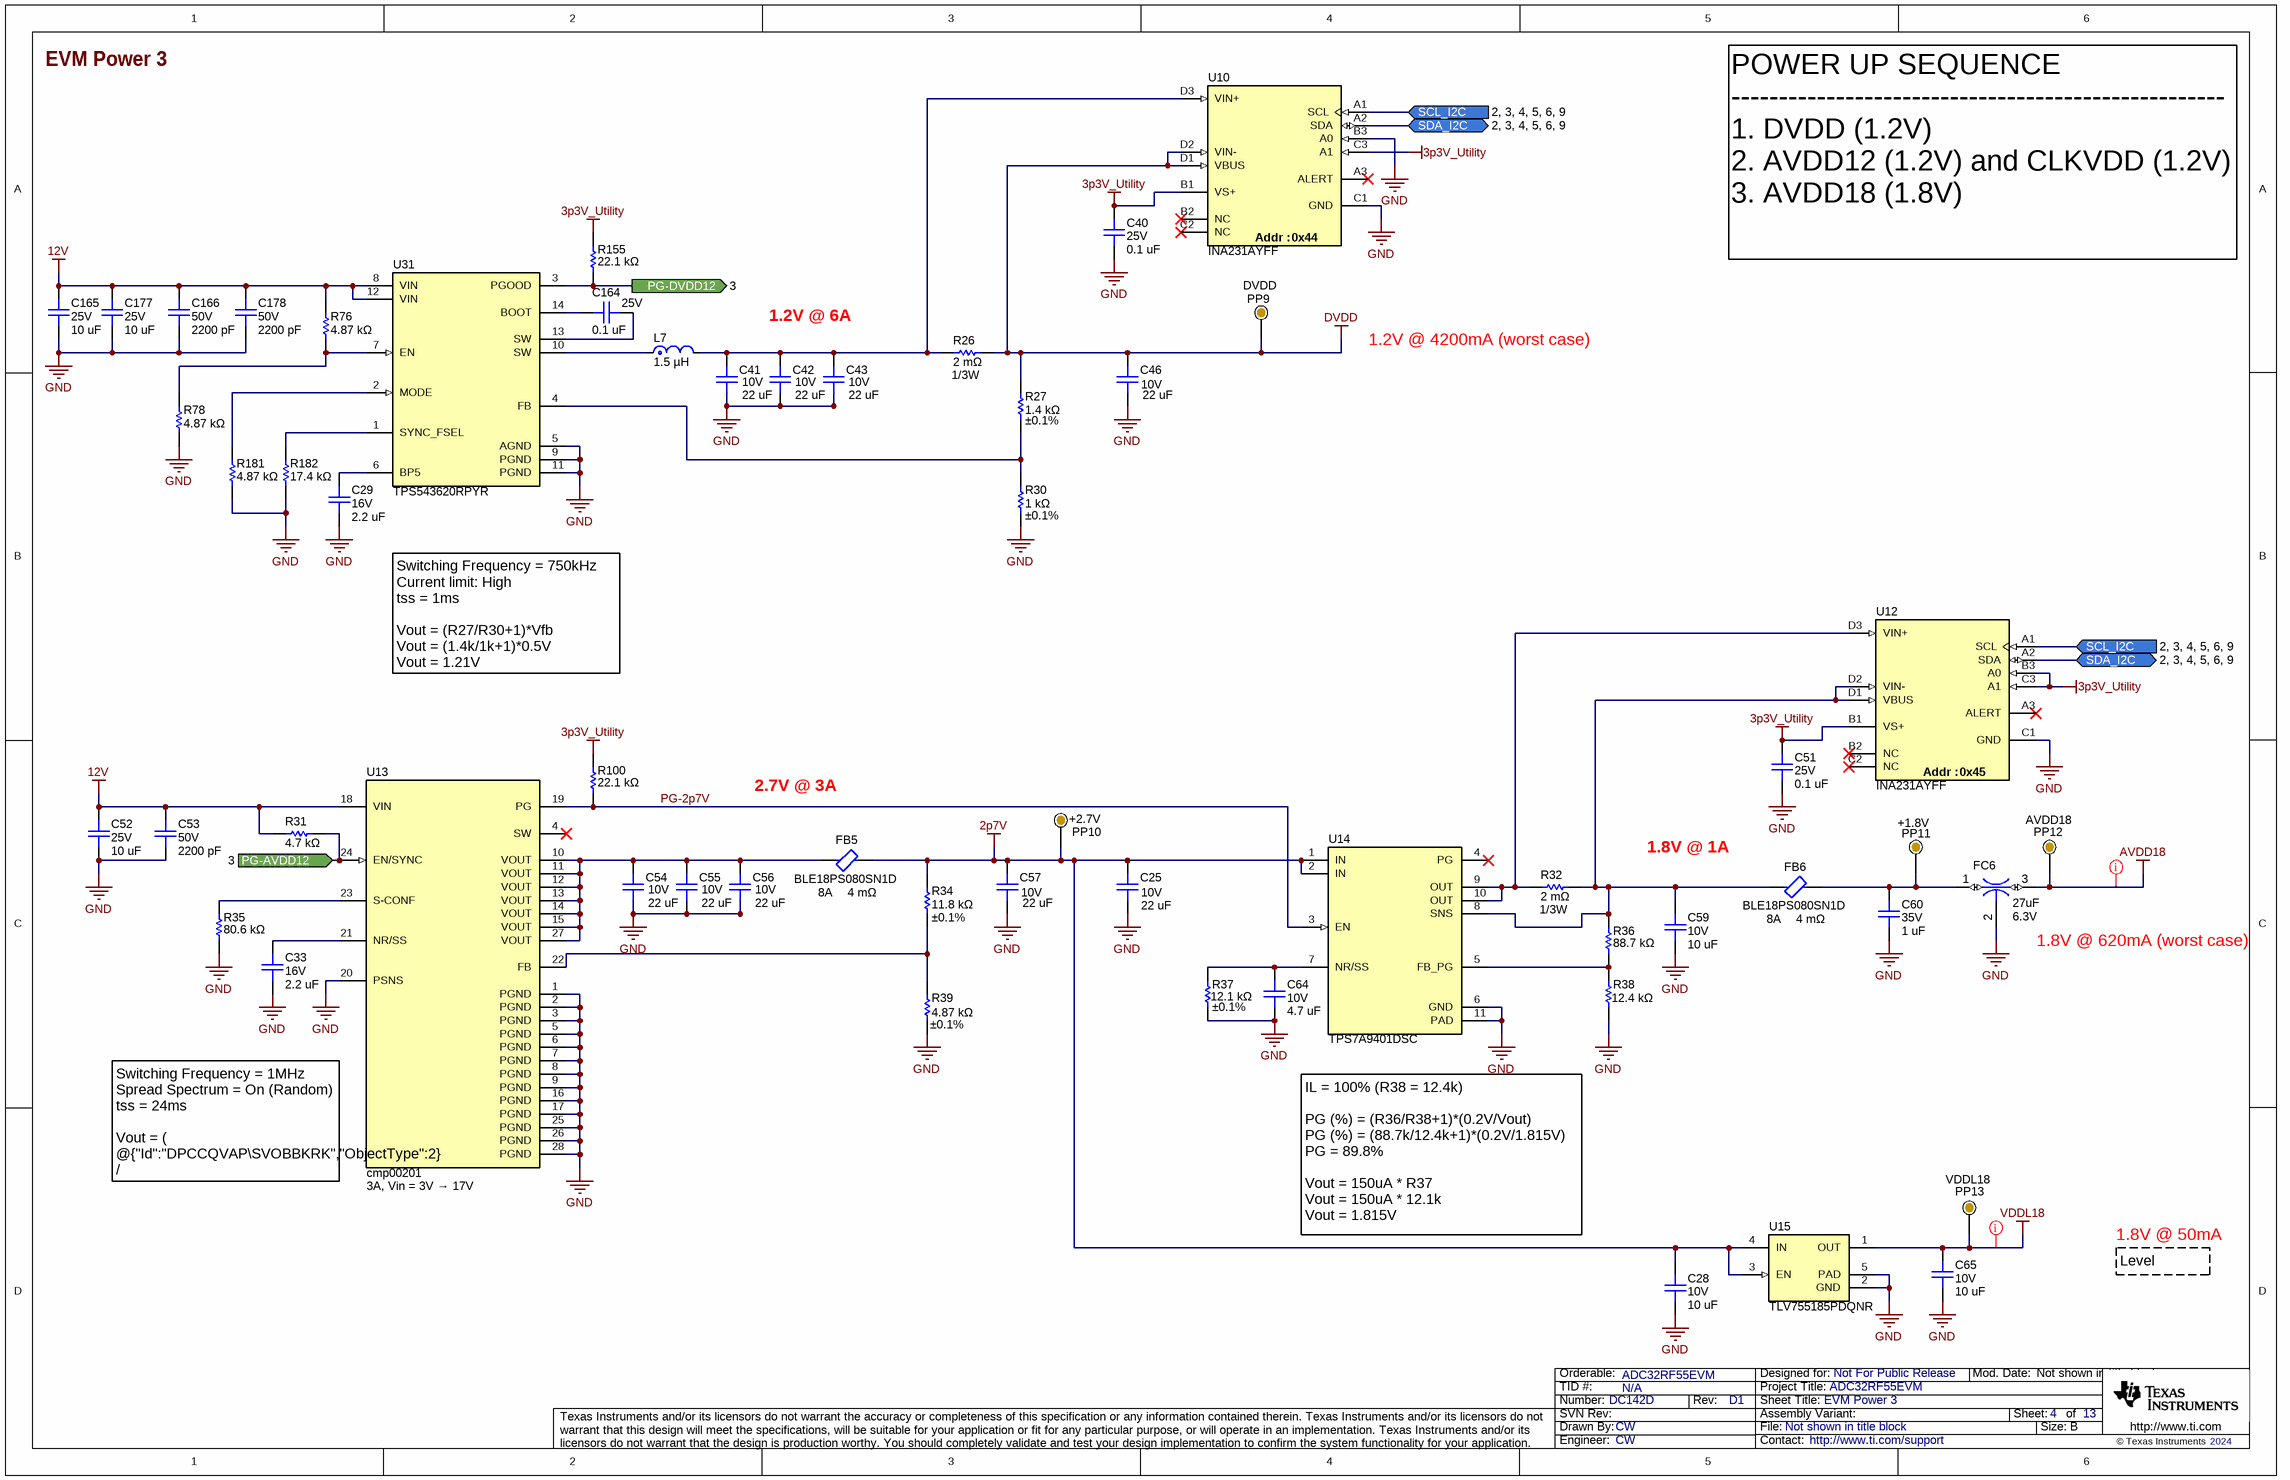
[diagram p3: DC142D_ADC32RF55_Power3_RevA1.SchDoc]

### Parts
C25  value 22 uF  Voltage - Rated: 10V  [0805L_cap]  (hidden comment: C2012X7S1A226M125AC)
C28  value 10 uF  Voltage - Rated: 10V  [0402L_cap]  (hidden comment: 0402ZD106MAT2A)
C29  value 2.2 uF  Voltage - Rated: 16V  [0402L_cap]  (hidden comment: C1005X6S1C225K050BC)
C33  value 2.2 uF  Voltage - Rated: 16V  [0402L_cap]  (hidden comment: C1005X6S1C225K050BC)
C40  value 0.1 uF  Voltage - Rated: 25V  [0402L_cap]  (hidden comment: 04023C104JAT2A)
C41  value 22 uF  Voltage - Rated: 10V  [0805L_cap]  (hidden comment: C2012X7S1A226M125AC)
C42  value 22 uF  Voltage - Rated: 10V  [0805L_cap]  (hidden comment: C2012X7S1A226M125AC)
C43  value 22 uF  Voltage - Rated: 10V  [0805L_cap]  (hidden comment: C2012X7S1A226M125AC)
C46  value 22 uF  Voltage - Rated: 10V  [0805L_cap]  (hidden comment: C2012X7S1A226M125AC)
C51  value 0.1 uF  Voltage - Rated: 25V  [0402L_cap]  (hidden comment: 04023C104JAT2A)
C52  value 10 uF  Voltage - Rated: 25V  [0805L_cap]  (hidden comment: C2012X7S1E106K125AC)
C53  value 2200 pF  Voltage - Rated: 50V  [0402L_cap]  (hidden comment: 04025C222JAT2A)
C54  value 22 uF  Voltage - Rated: 10V  [0805L_cap]  (hidden comment: C2012X7S1A226M125AC)
C55  value 22 uF  Voltage - Rated: 10V  [0805L_cap]  (hidden comment: C2012X7S1A226M125AC)
C56  value 22 uF  Voltage - Rated: 10V  [0805L_cap]  (hidden comment: C2012X7S1A226M125AC)
C57  value 22 uF  Voltage - Rated: 10V  [0805L_cap]  (hidden comment: C2012X7S1A226M125AC)
C59  value 10 uF  Voltage - Rated: 10V  [0402L_cap]  (hidden comment: 0402ZD106MAT2A)
C60  value 1 uF  Voltage - Rated: 35V  [0402L_cap]  (hidden comment: C1005X5R1V105K050BE)
C64  value 4.7 uF  Voltage - Rated: 10V  [0402L_cap]  (hidden comment: C1005X5R1A475K050BE)
C65  value 10 uF  Voltage - Rated: 10V  [0402L_cap]  (hidden comment: 0402ZD106MAT2A)
C164  value 0.1 uF  Voltage - Rated: 25V  [0201_cap]  (hidden comment: C0603X5R1E104K030BB)
C165  value 10 uF  Voltage - Rated: 25V  [0805L_cap]  (hidden comment: C2012X7S1E106K125AC)
C166  value 2200 pF  Voltage - Rated: 50V  [0402L_cap]  (hidden comment: 04025C222JAT2A)
C177  value 10 uF  Voltage - Rated: 25V  [0805L_cap]  (hidden comment: C2012X7S1E106K125AC)
C178  value 2200 pF  Voltage - Rated: 50V  [0402L_cap]  (hidden comment: 04025C222JAT2A)
FB5  BLE18PS080SN1D  Current: 8A  DCR: 4 mΩ  [0603L]
FB6  BLE18PS080SN1D  Current: 8A  DCR: 4 mΩ  [0603L]
FC6  value 27uF  Voltage - Rated: 6.3V  [NFM31PC]  (hidden comment: dcp00001)
L7  value 1.5 µH  [XGL4020]  (hidden comment: XGL4020-152MEC)
PP9  Text1: DVDD  [ProbePoint_TH_40mil]  (hidden comment: Probe Point)  (no BOM)
PP10  Text1: +2.7V  [ProbePoint_TH_40mil]  (hidden comment: Probe Point)  (no BOM)
PP11  Text1: +1.8V  [ProbePoint_TH_40mil]  (hidden comment: Probe Point)  (no BOM)
PP12  Text1: AVDD18  [ProbePoint_TH_40mil]  (hidden comment: Probe Point)  (no BOM)
PP13  Text1: VDDL18  [ProbePoint_TH_40mil]  (hidden comment: Probe Point)  (no BOM)
R26  value 2 mΩ  Power (Watts): 1/3W  [CCS0603FLxLxx]  (hidden comment: CSS0603FT2L00)
R27  value 1.4 kΩ  Tolerance: ±0.1%  [0402L]  (hidden comment: ERA-2AEB1401X)
R30  value 1 kΩ  Tolerance: ±0.1%  [0402L]  (hidden comment: ERA-2VEB1001X)
R31  value 4.7 kΩ  [0402L]  (hidden comment: ERJ-PA2F4701X)
R32  value 2 mΩ  Power (Watts): 1/3W  [CCS0603FLxLxx]  (hidden comment: CSS0603FT2L00)
R34  value 11.8 kΩ  Tolerance: ±0.1%  [0402L]  (hidden comment: ERA-2AEB1182X)
R35  value 80.6 kΩ  [0402L]  (hidden comment: ERJ-2RKF8062X)
R36  value 88.7 kΩ  [0402L]  (hidden comment: ERJ-2RKF8872X)
R37  value 12.1 kΩ  Tolerance: ±0.1%  [0402L]  (hidden comment: ERA-2APB1212X)
R38  value 12.4 kΩ  [0402L]  (hidden comment: ERJ-2RKF1242X)
R39  value 4.87 kΩ  Tolerance: ±0.1%  [0402L]  (hidden comment: ERA-2APB4871X)
R76  value 4.87 kΩ  [0402L]  (hidden comment: ERJ-2RKF4871X)
R78  value 4.87 kΩ  [0402L]  (hidden comment: ERJ-2RKF4871X)
R100  Resistance: 22.1 kΩ  [0402L]  (hidden comment: ERJ-2RKF2212X)
R155  Resistance: 22.1 kΩ  [0402L]  (hidden comment: ERJ-2RKF2212X)
R181  value 4.87 kΩ  [0402L]  (hidden comment: ERJ-2RKF4871X)
R182  value 17.4 kΩ  [0402L]  (hidden comment: ERJ-2RKF1742X)
U10  INA231AYFF  Address: 0x44  [YFF0012AKAD]
U12  INA231AYFF  Address: 0x45  [YFF0012AKAD]
U13  cmp00201  Text1: 3A, Vin = 3V → 17V  [RDU0028A]
U14  TPS7A9401DSC  [DSC0010]
U15  TLV755185PDQNR  [DQN0004A]
U31  TPS543620RPYR  [RPY0014A]

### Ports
PG-AVDD12 (in, see 3), PG-DVDD12 (out, see 3), SCL_I2C (in, see 2, 3, 4, 5, 6, 9), SDA_I2C (bidir, see 2, 3, 4, 5, 6, 9)

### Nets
2p7V: C25.2 C28.2 C57.2 FB5.2 PP10.1 R34.2 U14.1(IN) U14.2(IN) U15.3(EN) U15.4(IN)
3p3V_Utility: C40.2 C51.2 R100.2 R155.2 U10.B1(VS+) U10.C3(A1) U12.B1(VS+) U12.B3(A0) U12.C3(A1)
12V: C52.2 C53.2 C165.2 C166.2 C177.2 C178.2 R31.1 R76.2 U13.18(VIN) U31.8(VIN) U31.12(VIN)
AVDD18: FC6.3 PP12.1
DVDD: C46.2 PP9.1 R26.2 R27.2 U10.D1(VBUS) U10.D2(VIN-)
GND: C25.1 C28.1 C29.1 C33.1 C40.1 C41.1 C42.1 C43.1 C46.1 C51.1 C52.1 C53.1 C54.1 C55.1 C56.1 C57.1 C59.1 C60.1 C64.1 C65.1 C165.1 C166.1 C177.1 C178.1 FC6.2 R30.1 R35.1 R37.1 R38.1 R39.1 R78.1 R181.1 R182.1 U10.B3(A0) U10.C1(GND) U12.C1(GND) U13.1(PGND) U13.2(PGND) U13.3(PGND) U13.5(PGND) U13.6(PGND) U13.7(PGND) U13.8(PGND) U13.9(PGND) U13.16(PGND) U13.17(PGND) U13.20(PSNS) U13.25(PGND) U13.26(PGND) U13.28(PGND) U14.6(GND) U14.11(PAD) U15.2(GND) U15.5(PAD) U31.5(AGND) U31.9(PGND) U31.11(PGND)
VDDL18: C65.2 PP13.1 U15.1(OUT)
PG-2p7V: R100.1 U13.19(PG) U14.3(EN)
PG-AVDD12: R31.2 U13.24(EN/SYNC) ; port PG-AVDD12
PG-DVDD12: R155.1 U31.3(PGOOD) ; port PG-DVDD12
SCL_I2C: U10.A1(SCL) U12.A1(SCL) ; port SCL_I2C
SDA_I2C: U10.A2(SDA) U12.A2(SDA) ; port SDA_I2C
NetC29_2: C29.2 U31.6(BP5)
NetC33_2: C33.2 U13.21(NR/SS)
NetC41_2: C41.2 C42.2 C43.2 L7.2 R26.1 U10.D3(VIN+)
NetC54_2: C54.2 C55.2 C56.2 FB5.1 U13.10(VOUT) U13.11(VOUT) U13.12(VOUT) U13.13(VOUT) U13.14(VOUT) U13.15(VOUT) U13.27(VOUT)
NetC59_2: C59.2 FB6.1 R32.2 R36.2 U12.D1(VBUS) U12.D2(VIN-) U14.8(SNS)
NetC60_2: C60.2 FB6.2 FC6.1 PP11.1
NetC64_2: C64.2 R37.2 U14.7(NR/SS)
NetC164_1: C164.1 U31.13(SW)
NetC164_2: C164.2 U31.14(BOOT)
NetL7_1: L7.1 U31.10(SW)
NetR27_1: R27.1 R30.2 U31.4(FB)
NetR32_1: R32.1 U12.D3(VIN+) U14.9(OUT) U14.10(OUT)
NetR34_1: R34.1 R39.2 U13.22(FB)
NetR35_2: R35.2 U13.23(S-CONF)
NetR36_1: R36.1 R38.2 U14.5(FB_PG)
NetR76_1: R76.1 R78.2 U31.7(EN)
NetR181_2: R181.2 U31.2(MODE)
NetR182_2: R182.2 U31.1(SYNC_FSEL)

Not connected (* = marked no-connect by the designer): U10 A3(ALERT)* B2(NC)* C2(NC)*; U12 A3(ALERT)* B2(NC)* C2(NC)*; U13 4(SW)*; U14 4(PG)*

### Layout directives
net class Power: AVDD18, VDDL18

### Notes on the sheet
- POWER UP SEQUENCE
  ----------------------------------------------------
  1. DVDD (1.2V)
  2. AVDD12 (1.2V) and CLKVDD (1.2V)
  3. AVDD18 (1.8V)
- 1.2V @ 6A
- 1.2V @ 4200mA (worst case)
- Switching Frequency = 750kHz
  Current limit: High
  tss = 1ms
  Vout = (R27/R30+1)*Vfb
  Vout = (1.4k/1k+1)*0.5V
  Vout = 1.21V
- 2.7V @ 3A
- 1.8V @ 1A
- (near FC6) 1.8V @ 620mA (worst case)
- (near U13) Switching Frequency = 1MHz
  Spread Spectrum = On (Random)
  tss = 24ms
  Vout = ( @{"Id":"DPCCQVAP\SVOBBKRK","ObjectType":2} / @{"Id":"DPCCQVAP\PMASVVDB","ObjectType":2} +1)*Vfb
  Vout = (11.8k/4.87k+1)*0.8V
  Vout = 2.73V
- IL = 100% (R38 = 12.4k)
  PG (%) = (R36/R38+1)*(0.2V/Vout)
  PG (%) = (88.7k/12.4k+1)*(0.2V/1.815V)
  PG = 89.8%
  Vout = 150uA * R37
  Vout = 150uA * 12.1k
  Vout = 1.815V
- 1.8V @ 50mA
- Level Shifters

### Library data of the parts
C25 C41-C43 C46 C54-C57 = capcc09395: as C9 on sheet DC142D_ADC32RF55_Power1_RevA1
C28 C59 C65 = capcc09406: as C26 on sheet DC142D_ADC32RF55_Power2_RevA1
C29 C33 = capcc03154: as C30 on sheet DC142D_ADC32RF55_Power2_RevA1
C40 C51 = capcc01380: as C1 on sheet DC142D_ADC32RF55_Power1_RevA1
C52 C165 C177 = capcc03511: as C7 on sheet DC142D_ADC32RF55_Power1_RevA1
C53 C166 C178 = capcc04216: as C8 on sheet DC142D_ADC32RF55_Power1_RevA1
C60 = capcc02785: as C27 on sheet DC142D_ADC32RF55_Power2_RevA1
C64 = capcc03139: as C31 on sheet DC142D_ADC32RF55_Power2_RevA1
C164 = capcc01294: as C159 on sheet DC142D_ADC32RF55_Power2_RevA1
FB5 FB6 = dcp00004: as FB1 on sheet DC142D_ADC32RF55_Power1_RevA1
FC6 = dcp00001: as FC1 on sheet DC142D_ADC32RF55_Power1_RevA1
L7 = LSMT56800072: FIXED IND 1.5UH 11.1A 14.3 MOHM; Manufacturer: COILCRAFT; CompType: Inductor Power; Tolerance: ±20%; Current - Saturation (Isat): 7.5A; DC Resistance (DCR): 14.3mOhm Max; Inductance Frequency - Test: 1 MHz; Frequency - Self Resonant: 45MHz; SizeX_mm: 4; SizeZ_mm: 2.1
PP9-PP13 = cmp00025: as PP1 on sheet DC142D_ADC32RF55_Power1_RevA1
R26 R32 = OtherRs00002: as R1 on sheet DC142D_ADC32RF55_Power1_RevA1
R27 = RSMD040200167: RES SMD 1.4K OHM 0.1% 1/16W 0402; Manufacturer: Panasonic Electronic Components; CompType: Resistor SMD; Power (Watts): 0.063W, 1/16W; Temperature Coefficient: ±25ppm/°C; SizeX_mm: 1; SizeY_mm: 0.5; SizeZ_mm: 0.4
R30 = RSMD040200009: RES 1K OHM 0.1% 1/10W 0402; Manufacturer: Panasonic Electronic Components; CompType: Resistor SMD; Power (Watts): 0.1W, 1/10W; Temperature Coefficient: ±25ppm/°C; SizeX_mm: 1; SizeY_mm: 0.5; SizeZ_mm: 0.4
R31 = RSMD040202587: as R8 on sheet DC142D_ADC32RF55_Power1_RevA1
R34 = RSMD040200444: as R21 on sheet DC142D_ADC32RF55_Power2_RevA1
R35 = RSMD040203748: as R9 on sheet DC142D_ADC32RF55_Power1_RevA1
R36 = RSMD040203879: RES SMD 88.7K OHM 1% 1/10W 0402; Manufacturer: Panasonic Electronic Components; CompType: Resistor SMD; Power (Watts): 0.1W, 1/10W; Temperature Coefficient: ±100ppm/°C; SizeX_mm: 1; SizeY_mm: 0.5; SizeZ_mm: 0.4
R37 = RSMD040200541: RES SMD 12.1KOHM 0.1% 1/16W 0402; Manufacturer: Panasonic Electronic Components; CompType: Resistor SMD; Power (Watts): 0.063W, 1/16W; Temperature Coefficient: ±15ppm/°C; SizeX_mm: 1; SizeY_mm: 0.5; SizeZ_mm: 0.4
R38 = RSMD040200547: as R18 on sheet DC142D_ADC32RF55_Power2_RevA1
R39 = RSMD040202614: as R10 on sheet DC142D_ADC32RF55_Power1_RevA1
R76 R78 R181 = RSMD040202616: as R5 on sheet DC142D_ADC32RF55_Power1_RevA1
R100 R155 = RSMD040201481: as R23 on sheet DC142D_ADC32RF55_Power2_RevA1
R182 = RSMD040200983: RES SMD 17.4K OHM 1% 1/10W 0402; Manufacturer: Panasonic Electronic Components; CompType: Resistor SMD; Power (Watts): 0.1W, 1/10W; Temperature Coefficient: ±100ppm/°C; SizeX_mm: 1; SizeY_mm: 0.5; SizeZ_mm: 0.4
U10 U12 = INA231AYFF: as U30 on sheet DC142D_ADC32RF55_Power1_RevA1
U13 = cmp00201: 3-V to 17-V, 3-A Low-Noise and Low-Ripple Buck Power Module with Integrated Ferrite Bead Filter Compensation; PartNumber: TPSM82913RDU; Part Number: TPSM82913RDUR; Manufacturer: Texas Instruments; Switching Frequency: 1/2.2MHz; Max Duty Cycle: 100%; Output Voltage: 0.8-5.5V; Standoff Height: 0mm; CompType: Switcher; Number Of Outputs: 1; Max Supply Voltage: 17V; AEC Category: Q200; TJmax_C: +125°C; Nominal Supply Current: 5mA; Output Type: AdjustableProgrammable; Min Supply Voltage: 3V; AEC Qualified: No
U14 = cmp00169: as U7 on sheet DC142D_ADC32RF55_Power2_RevA1
U15 = TLV755185PDQNR: 500-mA high-PSRR low-IQ low-dropout (LDO) voltage regulator with enable (1.8V Fixed output); Mfr_Name: Texas Instruments
U31 = cmp00293: 4-V to 18-V Input, 6-A Synchronous SWIFT™ Step-Down Converter with Internally Compensated Advanced Current Mode Control; Mfr_Name: Texas Instruments; CompType: Switcher

## Sheet DC142D_ADC32RF55_USB_RevA1.SchDoc: USB Interface
size 431 x 279 mm; Date: Not shown in title block; ApprovedBy: Not shown in title block; CheckedBy: Not shown in title block; Author: Not shown in title block; CompanyName: Not shown in title block; DrawnBy: CW; Engineer: Not shown in title block; Organization: Not shown in title block; Address1: Not shown in title block; Address2: Not shown in title block; Address3: Not shown in title block; Address4: Not shown in title block; DocumentNumber: 11; Revision: Use project parameter SCH_Rev; SheetNumber: 5; SheetTotal: 13; PageSetup: Record=PageOptions¦CenterHorizontal=True¦CenterVertical=True¦PrintScale=1.00¦XCorrection=1.00¦YCorrection=1.00¦PrintKind=0¦BorderSize=5000000¦LeftOffset=0¦BottomOffset=0¦Orientation=2¦PaperLength=1000¦PaperWidth=1000¦Scale=100¦PaperSource=15¦PrintQuality=600¦MediaType=1¦DitherType=10¦PaperKind=Letter¦PrintScaleMode=1
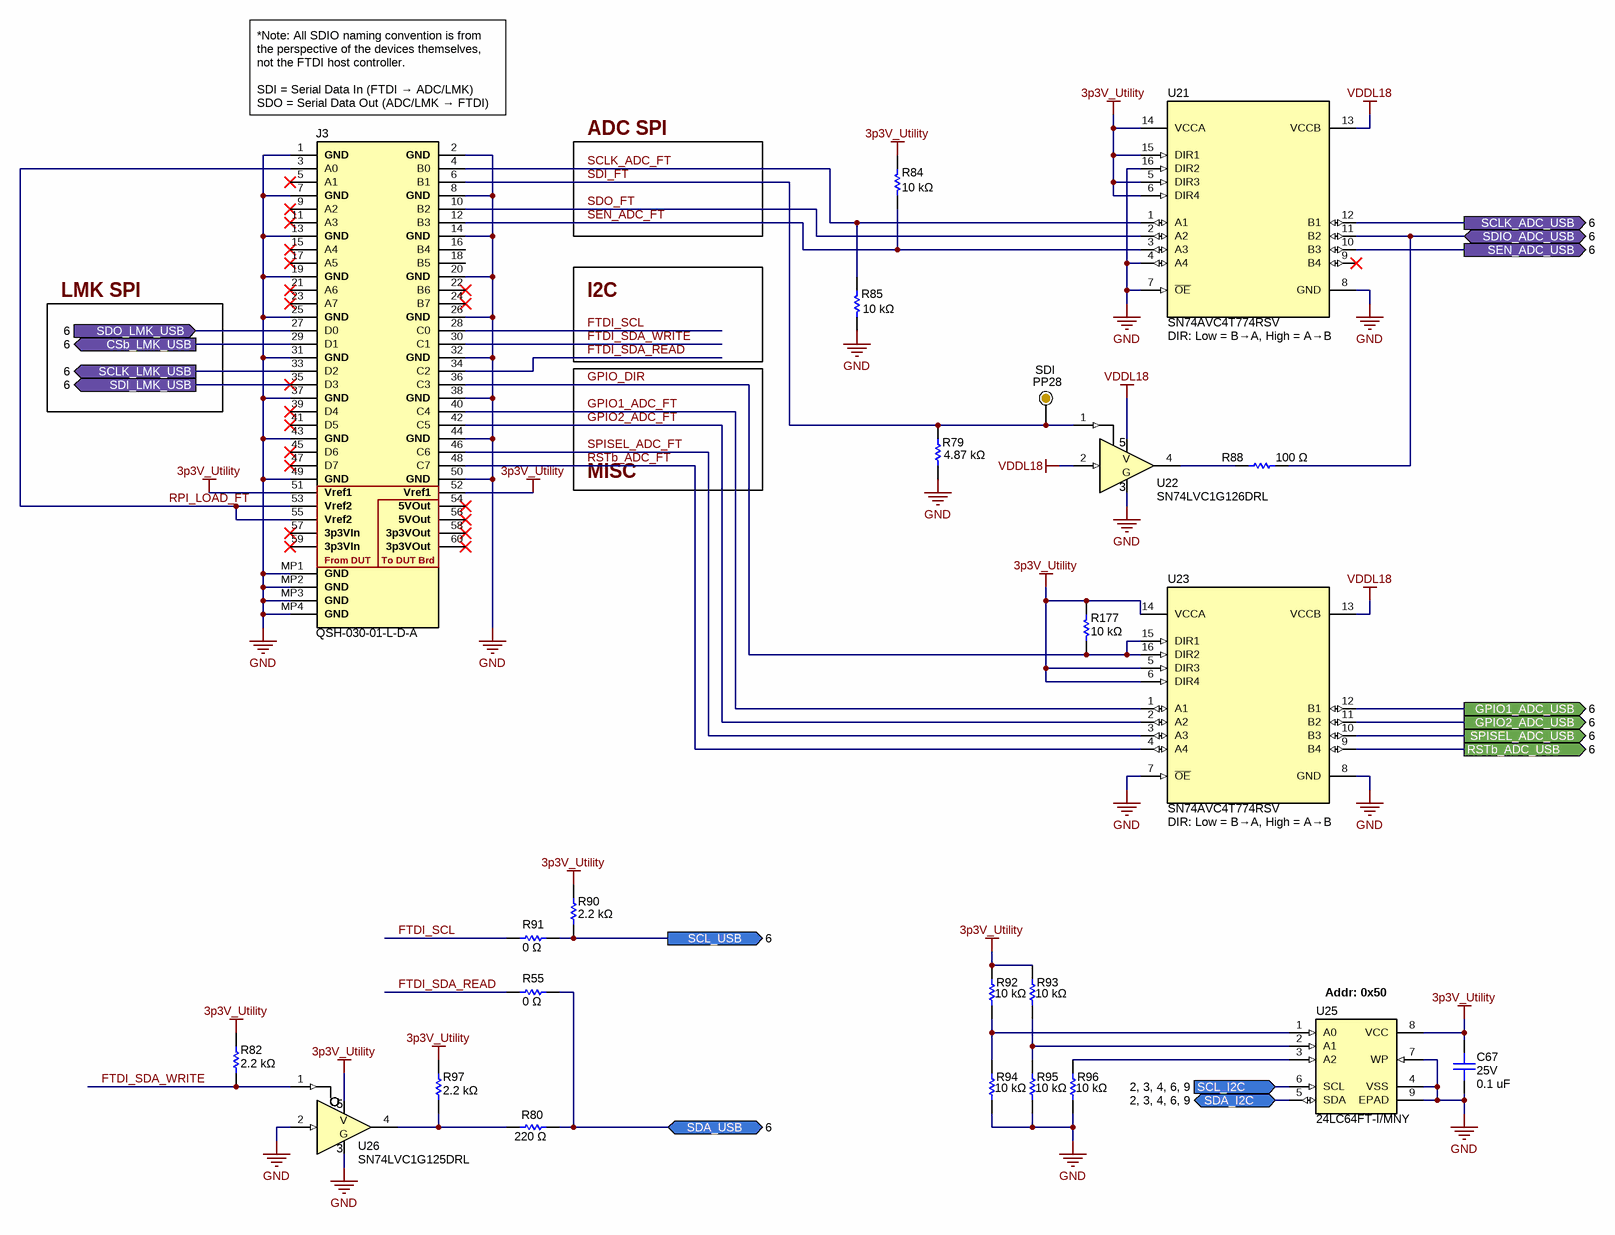
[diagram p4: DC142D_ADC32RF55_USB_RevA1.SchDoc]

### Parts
C67  value 0.1 uF  Voltage - Rated: 25V  [0201_cap]  (hidden comment: C0603X5R1E104K030BB)
J3  QSH-030-01-L-D-A  [FTDI_Dongle_001]
PP28  Text1: SDI  [ProbePoint_TH_40mil]  (hidden comment: Probe Point)  (no BOM)
R55  value 0 Ω  [0201]  (hidden comment: ERJ-1GN0R00C)
R79  value 4.87 kΩ  [0402L]  (hidden comment: ERJ-2RKF4871X)
R80  value 220 Ω  [0201]  (hidden comment: ERJ-1GNF2200C)
R82  value 2.2 kΩ  [0201]  (hidden comment: ERJ-1GNF2201C)
R84  value 10 kΩ  [0201]  (hidden comment: ERJ-1GNF1002C)
R85  value 10 kΩ  [0201]  (hidden comment: ERJ-1GNF1002C)
R88  value 100 Ω  [0201]  (hidden comment: ERJ-1GNF1000C)
R90  value 2.2 kΩ  [0201]  (hidden comment: ERJ-1GNF2201C)
R91  value 0 Ω  [0201]  (hidden comment: ERJ-1GN0R00C)
R92  value 10 kΩ  [0201]  (hidden comment: ERJ-1GNF1002C)
R93  value 10 kΩ  [0201]  (hidden comment: ERJ-1GNF1002C)
R94  value 10 kΩ  [0201]  (hidden comment: ERJ-1GNF1002C)
R95  value 10 kΩ  [0201]  (hidden comment: ERJ-1GNF1002C)
R96  value 10 kΩ  [0201]  (hidden comment: ERJ-1GNF1002C)
R97  value 2.2 kΩ  [0201]  (hidden comment: ERJ-1GNF2201C)
R177  value 10 kΩ  [0201]  (hidden comment: ERJ-1GNF1002C)
U21  SN74AVC4T774RSV  Text1: DIR: Low = B→A, High = A→B  [RSV0016A]
U22  SN74LVC1G126DRL  [DRL0005A]
U23  SN74AVC4T774RSV  Text1: DIR: Low = B→A, High = A→B  [RSV0016A]
U25  24LC64FT-I/MNY  [TDFN8]
U26  SN74LVC1G125DRL  [DRL0005A]

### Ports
CSb_LMK_USB (out, see 6), GPIO1_ADC_USB (out, see 6), GPIO2_ADC_USB (out, see 6), RSTb_ADC_USB (out, see 6), SCL_I2C (in, see 2, 3, 4, 6, 9), SCL_USB (out, see 6), SCLK_ADC_USB (out, see 6), SCLK_LMK_USB (out, see 6), SDA_I2C (bidir, see 2, 3, 4, 6, 9), SDA_USB (bidir, see 6), SDI_LMK_USB (out, see 6), SDIO_ADC_USB (bidir, see 6), SDO_LMK_USB (in, see 6), SEN_ADC_USB (out, see 6), SPISEL_ADC_USB (out, see 6)

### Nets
3p3V_Utility: C67.2 J3.51(Vref1) J3.52(Vref1) R82.2 R84.2 R90.2 R92.1 R93.1 R97.2 R177.1 U21.5(DIR3) U21.6(DIR4) U21.14(VCCA) U21.15(DIR1) U23.5(DIR3) U23.6(DIR4) U23.14(VCCA) U25.8(VCC) U26.5(VCC)
GND: C67.1 J3.1(GND) J3.2(GND) J3.7(GND) J3.8(GND) J3.13(GND) J3.14(GND) J3.19(GND) J3.20(GND) J3.25(GND) J3.26(GND) J3.31(GND) J3.32(GND) J3.37(GND) J3.38(GND) J3.43(GND) J3.44(GND) J3.49(GND) J3.50(GND) J3.MP1(GND) J3.MP2(GND) J3.MP3(GND) J3.MP4(GND) R79.2 R85.1 R94.2 R95.2 R96.2 U21.4(A4) U21.7(~{OE}) U21.8(GND) U21.16(DIR2) U22.3(GND) U23.7(~{OE}) U23.8(GND) U25.4(VSS) U25.7(WP) U25.9(EPAD) U26.2(A) U26.3(GND)
VDDL18: U21.13(VCCB) U22.2(A) U22.5(VCC) U23.13(VCCB)
CSb_LMK_USB: J3.29(D1) ; port CSb_LMK_USB
FTDI_SCL: J3.28(C0) R91.1
FTDI_SDA_READ: J3.34(C2) R55.1
FTDI_SDA_WRITE: J3.30(C1) R82.1 U26.1(~{OE})
GPIO1_ADC_FT: J3.40(C4) U23.1(A1)
GPIO1_ADC_USB: U23.12(B1) ; port GPIO1_ADC_USB
GPIO2_ADC_FT: J3.42(C5) U23.2(A2)
GPIO2_ADC_USB: U23.11(B2) ; port GPIO2_ADC_USB
GPIO_DIR: J3.36(C3) R177.2 U23.15(DIR1) U23.16(DIR2)
RPI_LOAD_FT: J3.3(A0) J3.53(Vref2) J3.55(Vref2)
RSTb_ADC_FT: J3.48(C7) U23.4(A4)
RSTb_ADC_USB: U23.9(B4) ; port RSTb_ADC_USB
SCL_I2C: U25.6(SCL) ; port SCL_I2C
SCL_USB: R90.1 R91.2 ; port SCL_USB
SCLK_ADC_FT: J3.4(B0) R85.2 U21.1(A1)
SCLK_ADC_USB: U21.12(B1) ; port SCLK_ADC_USB
SCLK_LMK_USB: J3.33(D2) ; port SCLK_LMK_USB
SDA_I2C: U25.5(SDA) ; port SDA_I2C
SDA_USB: R55.2 R80.2 ; port SDA_USB
SDI_FT: J3.6(B1) PP28.1 R79.1 U22.1(~{OE})
SDI_LMK_USB: J3.35(D3) ; port SDI_LMK_USB
SDIO_ADC_USB: R88.2 U21.11(B2) ; port SDIO_ADC_USB
SDO_FT: J3.10(B2) U21.2(A2)
SDO_LMK_USB: J3.27(D0) ; port SDO_LMK_USB
SEN_ADC_FT: J3.12(B3) R84.1 U21.3(A3)
SEN_ADC_USB: U21.10(B3) ; port SEN_ADC_USB
SPISEL_ADC_FT: J3.46(C6) U23.3(A3)
SPISEL_ADC_USB: U23.10(B3) ; port SPISEL_ADC_USB
NetR80_1: R80.1 R97.1 U26.4(Y)
NetR88_1: R88.1 U22.4(Y)
NetR92_2: R92.2 R94.1 U25.1(A0)
NetR93_2: R93.2 R95.1 U25.2(A1)
NetR96_1: R96.1 U25.3(A2)

Not connected (* = marked no-connect by the designer): J3 5(A1)* 9(A2)* 11(A3)* 15(A4)* 16(B4) 17(A5)* 18(B5) 21(A6)* 22(B6)* 23(A7)* 24(B7)* 39(D4)* 41(D5)* 45(D6)* 47(D7)* 54(5VOut)* 56(5VOut)* 57(3p3VIn)* 58(3p3VOut)* 59(3p3VIn)* 60(3p3VOut)*; U21 9(B4)*

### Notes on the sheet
- (near J3) *Note: All SDIO naming convention is from the perspective of the devices themselves, not the FTDI host controller.
  SDI = Serial Data In (FTDI → ADC/LMK)
  SDO = Serial Data Out (ADC/LMK → FTDI)
- ADC SPI
- LMK SPI
- I2C
- MISC
- (near U25) Addr: 0x50

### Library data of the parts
C67 = capcc01294: CAP CER 0.1UF 25V X5R 0201; Manufacturer: TDK Corporation; CompType: Capacitor Ceramic; Tolerance: ±10%; SizeX_mm: 0.6; SizeY_mm: 0.3; SizeZ_mm: 0.33
J3 = cmp00061: FTDI Dongle EVM Mating connector and standoff holes; Manufacturer: Samtec
PP28 = cmp00025: as PP1 on sheet DC142D_ADC32RF55_Power1_RevA1
R55 R91 = RSMD020101699: RES SMD 0 OHM JUMPER 1/20W 0201; Manufacturer: Panasonic Electronic Components; CompType: Resistor SMD; Power (Watts): 0.05W, 1/20W
R79 = RSMD040202616: as R5 on sheet DC142D_ADC32RF55_Power1_RevA1
R80 = RSMD020100147: RES SMD 220 OHM 1% 1/20W 0201; Manufacturer: Panasonic Electronic Components; CompType: Resistor SMD; Power (Watts): 0.05W, 1/20W; Temperature Coefficient: ±200ppm/°C
R82 R90 R97 = RSMD020100606: RES SMD 2.2K OHM 1% 1/20W 0201; Manufacturer: Panasonic Electronic Components; CompType: Resistor SMD; Power (Watts): 0.05W, 1/20W; Temperature Coefficient: ±200ppm/°C
R84 R85 R92-R96 R177 = RSMD020100762: RES SMD 10K OHM 1% 1/20W 0201; Manufacturer: Panasonic Electronic Components; CompType: Resistor SMD; Power (Watts): 0.05W, 1/20W; Temperature Coefficient: ±200ppm/°C
R88 = RSMD020100289: RES SMD 100 OHM 1% 1/20W 0201; Manufacturer: Panasonic Electronic Components; CompType: Resistor SMD; Power (Watts): 0.05W, 1/20W; Temperature Coefficient: ±200ppm/°C
U21 U23 = cmp00171: Translation - Voltage Levels 4-bit dual-supply bus transceiver with 3-state outputs and independent direction control inputs; Manufacturer: Texas Instruments; Alt PartNumber: SN74AXC4T774RSV; CompType: Level Shifter
U22 = SN74LVC1G126DRL: Single Bus Buffer Gate With 3-State Outputs. Active high enable.; Manufacturer: Texas Instruments
U25 = cmp00154: EEPROM 64K 8KX8 1.8V SER EE IND 1/4AWP RPO; Manufacturer: Microchip
U26 = cmp00472: Single Bus Buffer Gate With 3-State Outputs; Manufacturer: Texas Instruments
